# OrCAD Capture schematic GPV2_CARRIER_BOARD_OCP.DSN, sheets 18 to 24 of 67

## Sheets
18 023 PCIE SWITCH UART: size C
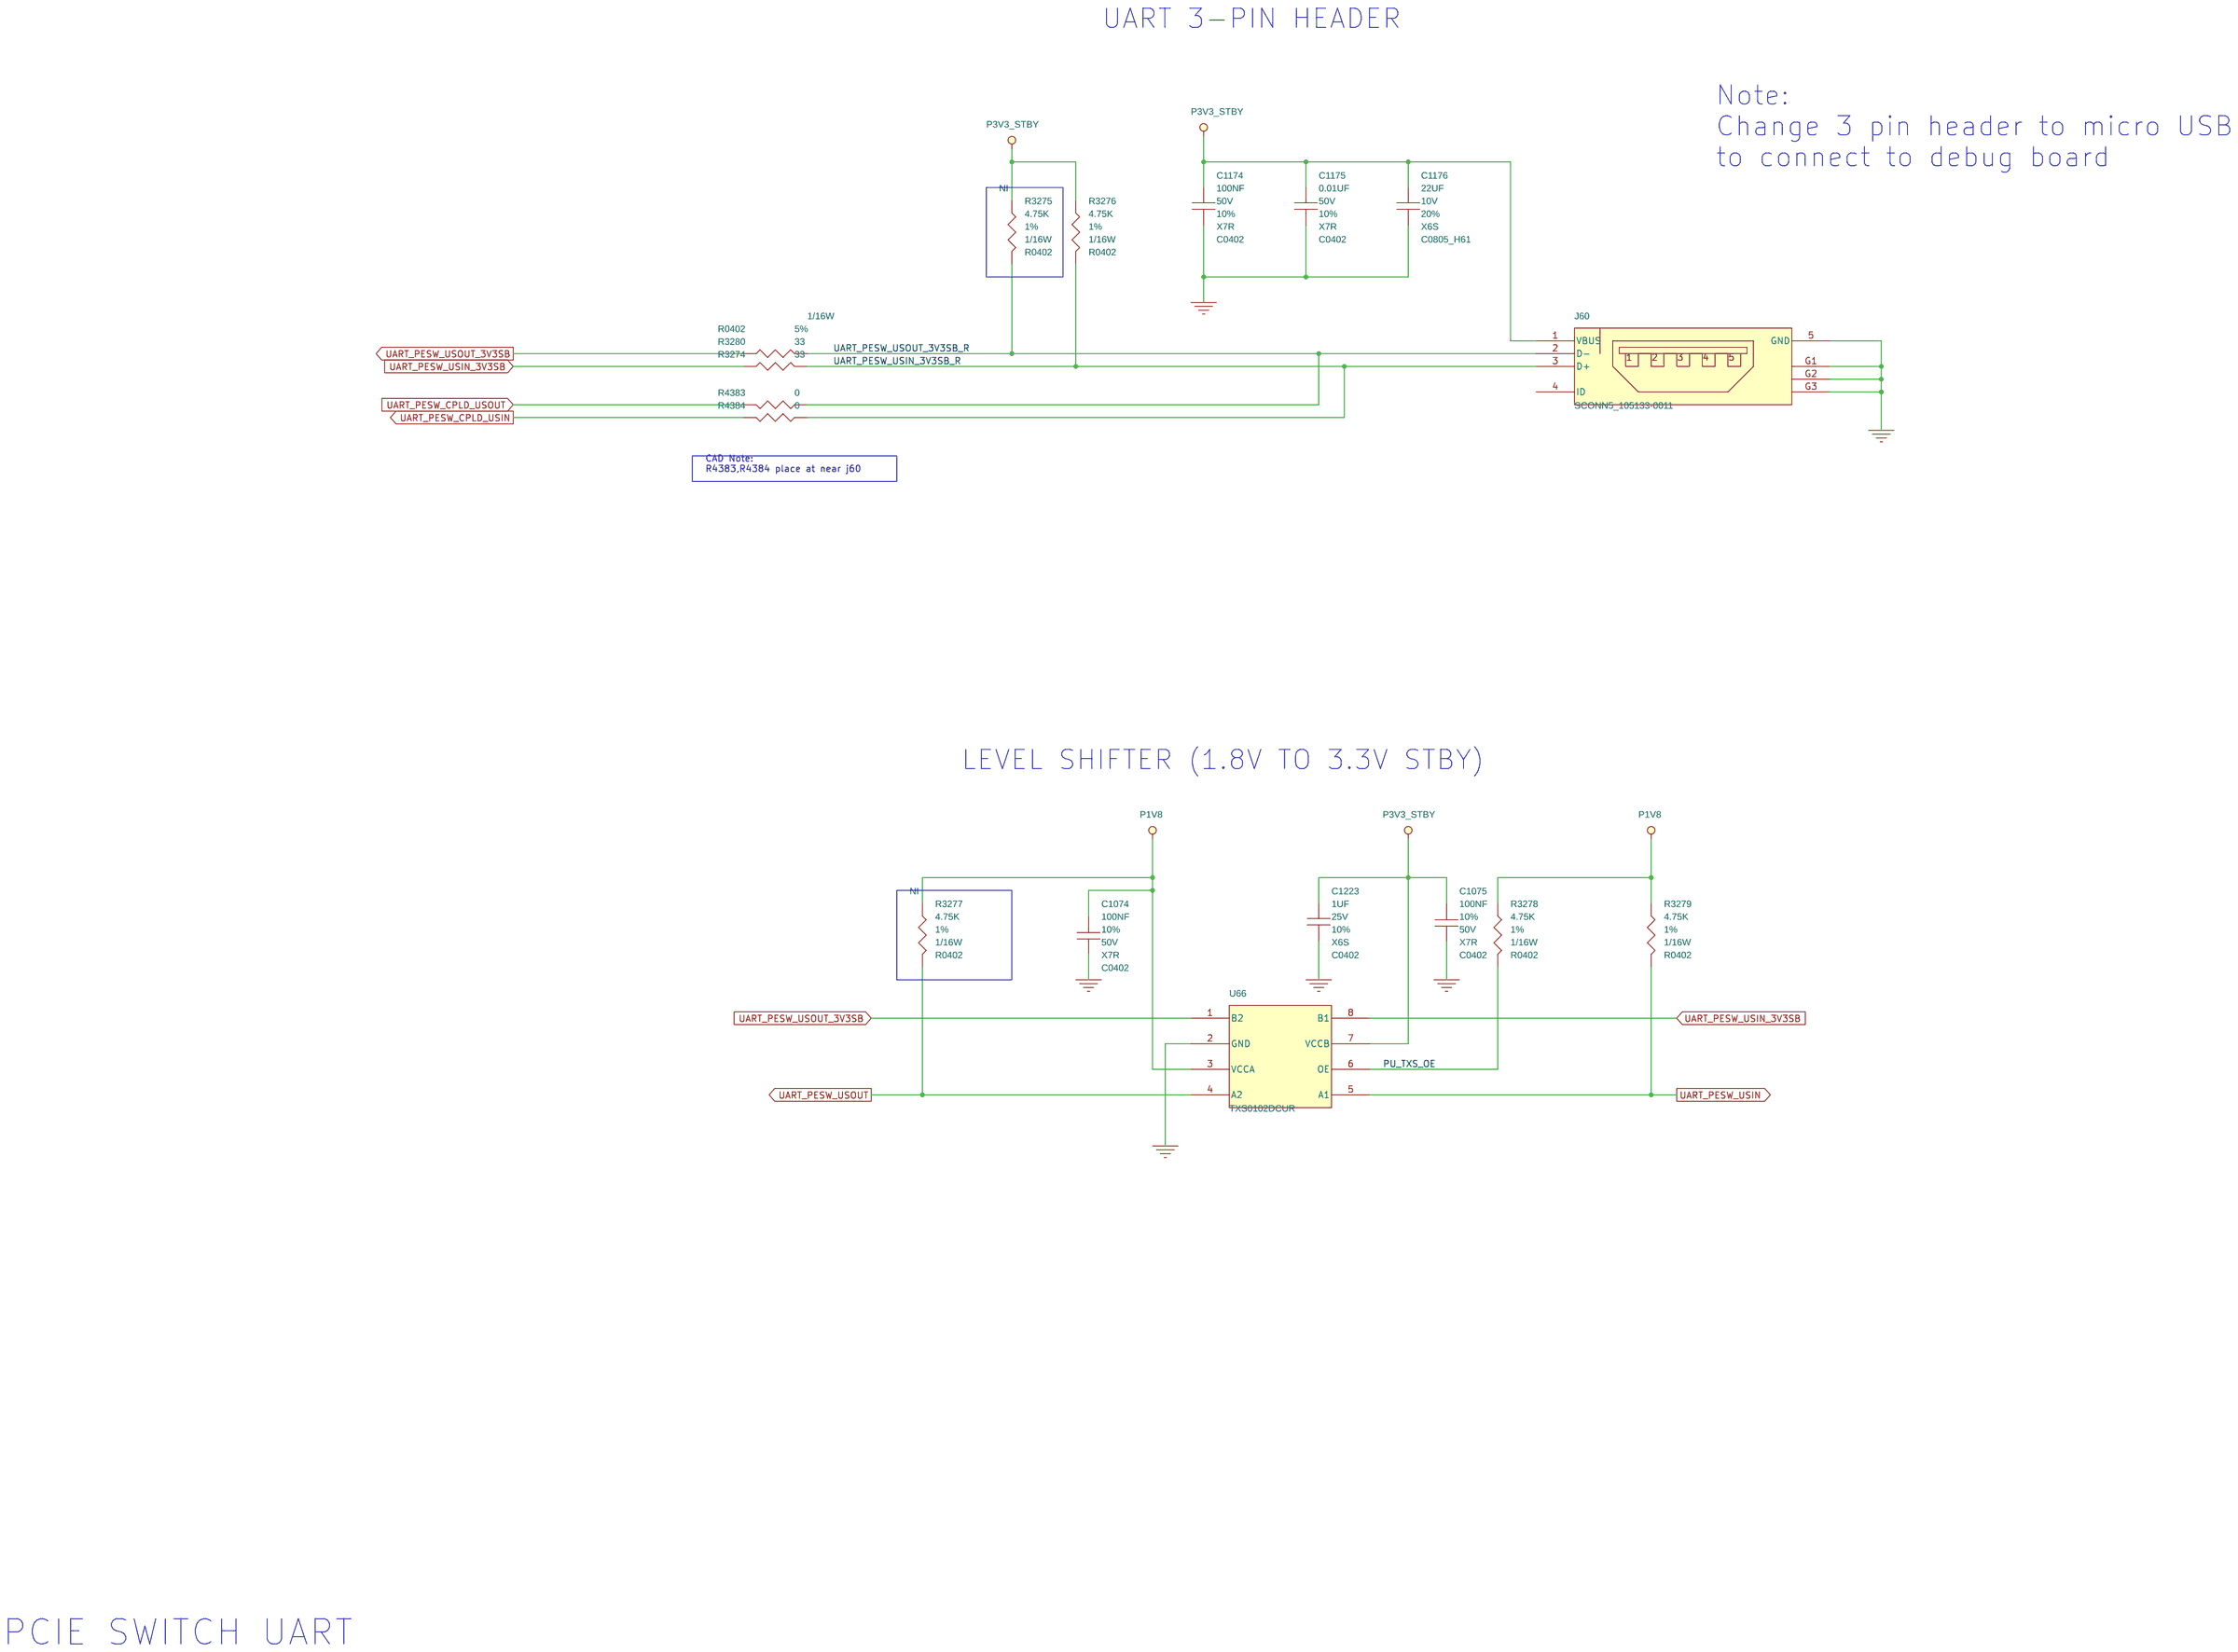
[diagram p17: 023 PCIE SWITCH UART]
19 024 100MHz CLOCK GEN: size C
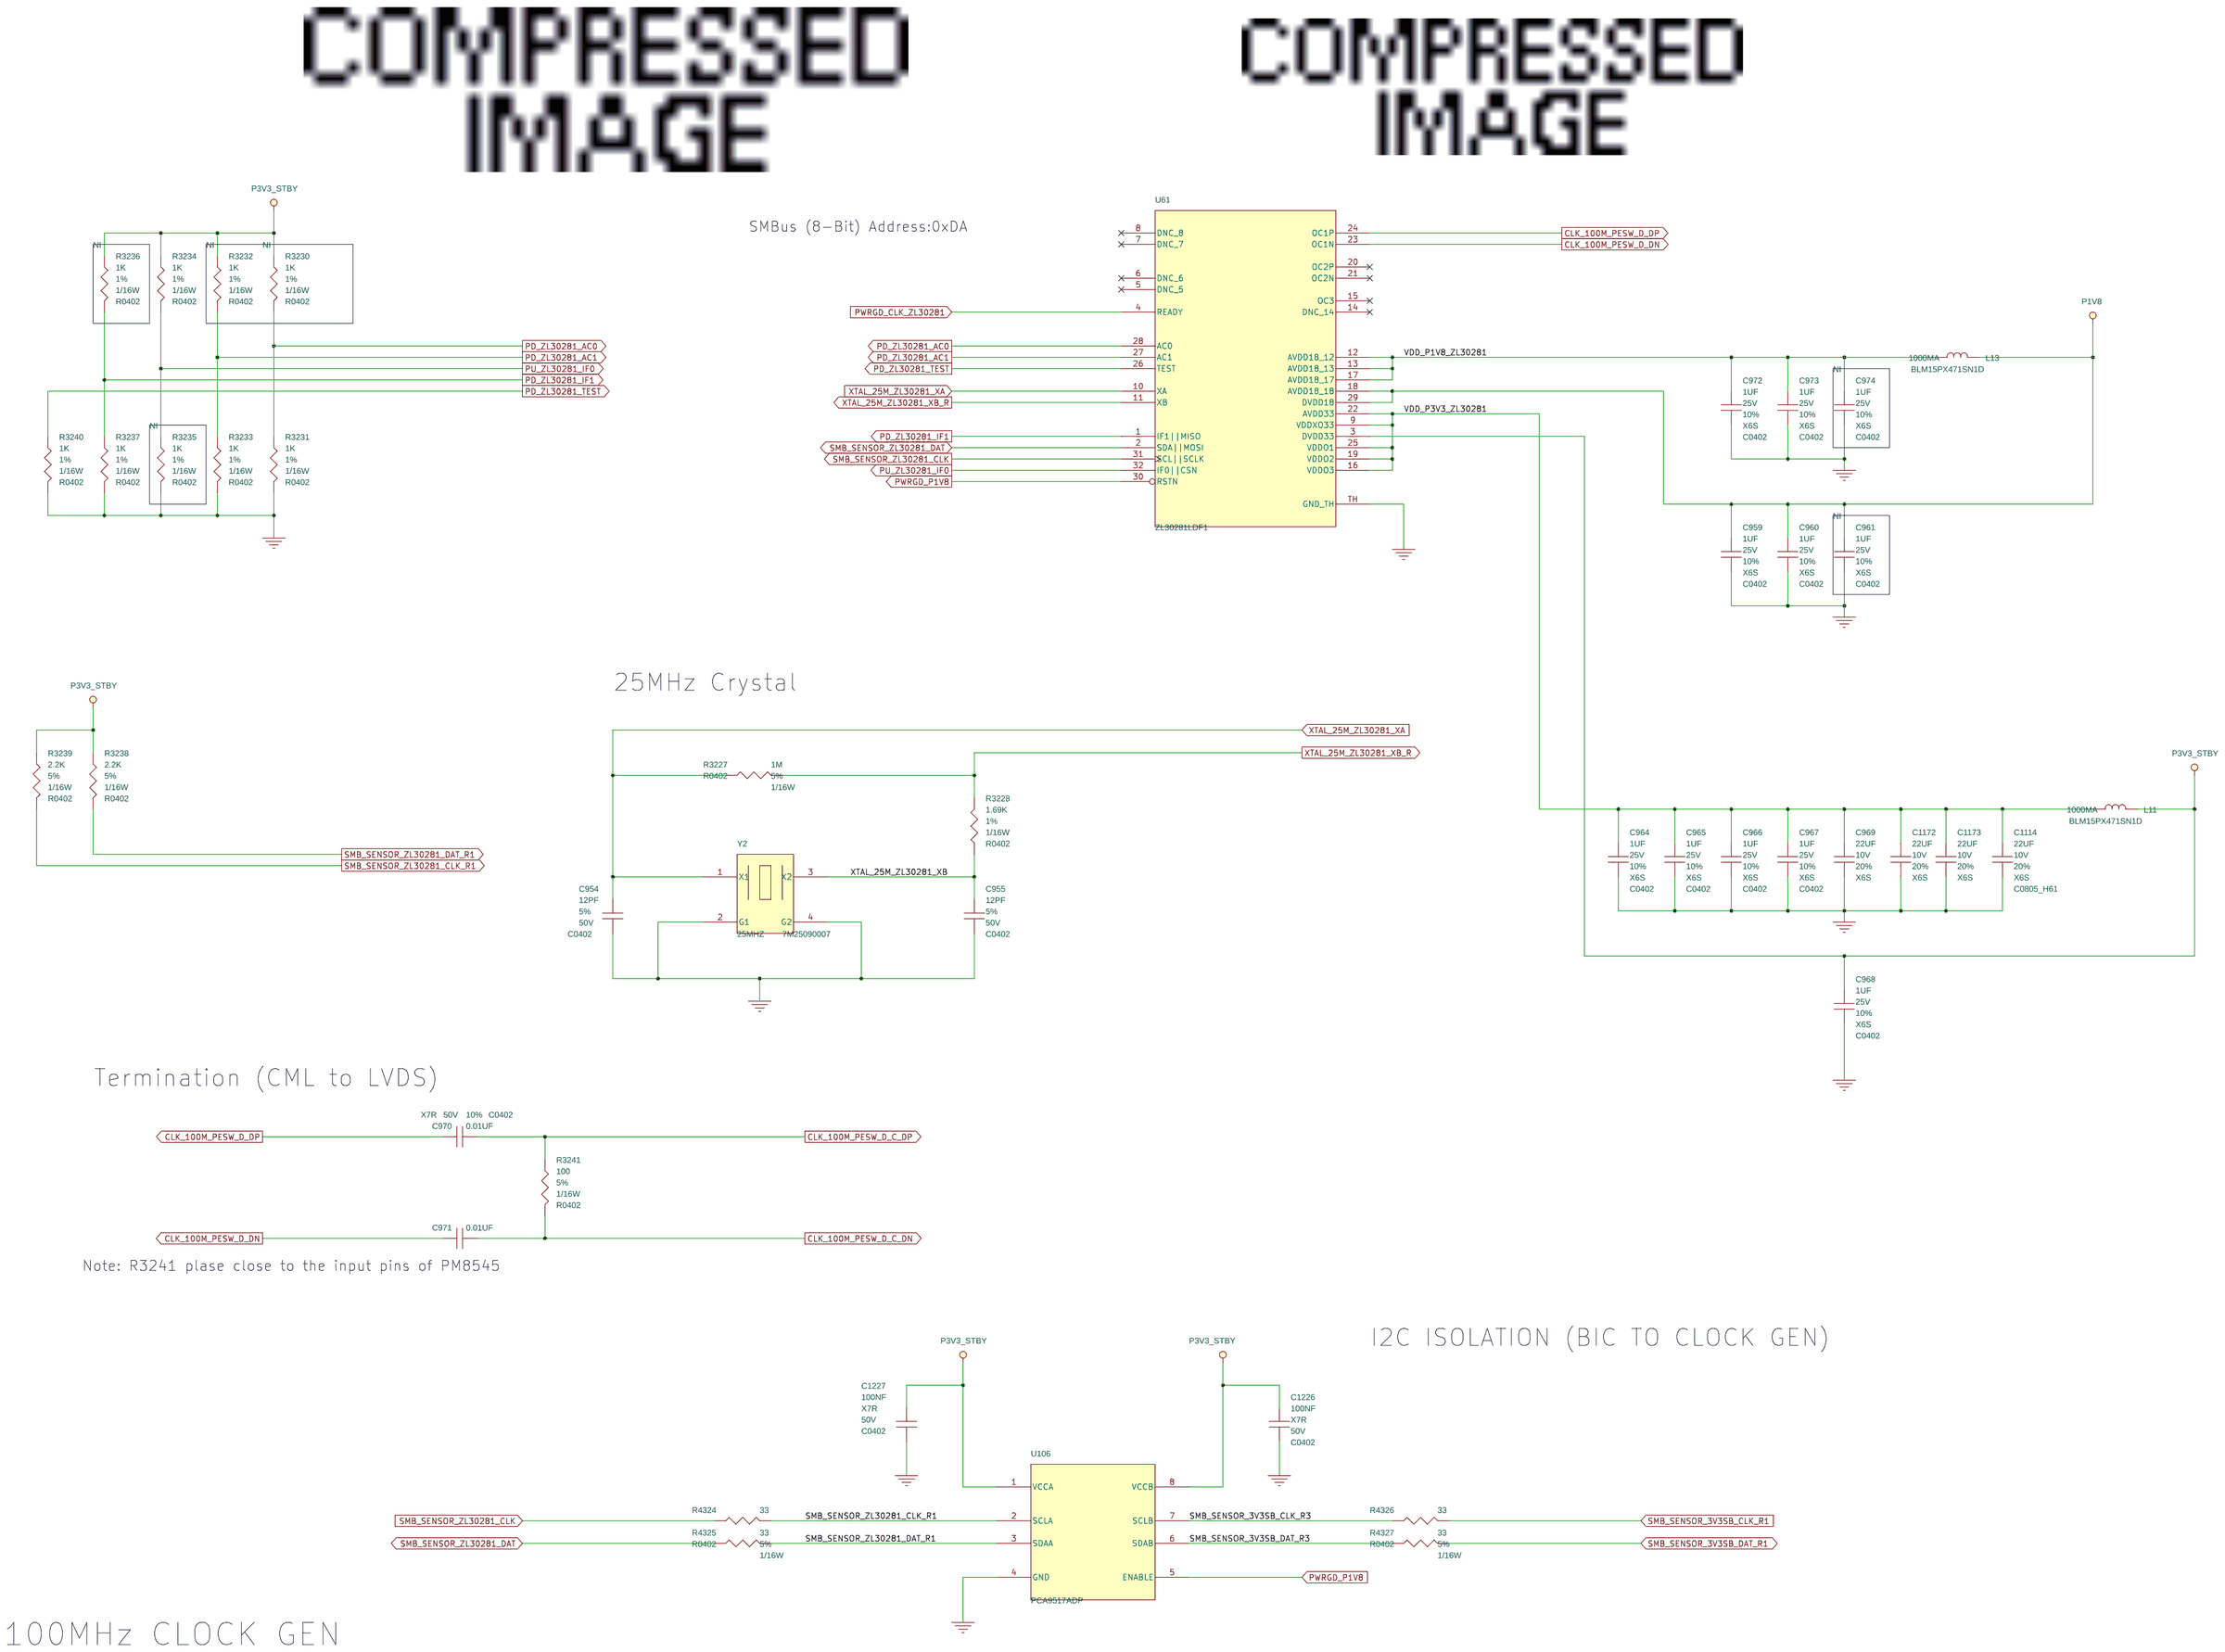
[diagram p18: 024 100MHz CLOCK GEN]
20 025 CLOCK BUFFER 1: size C
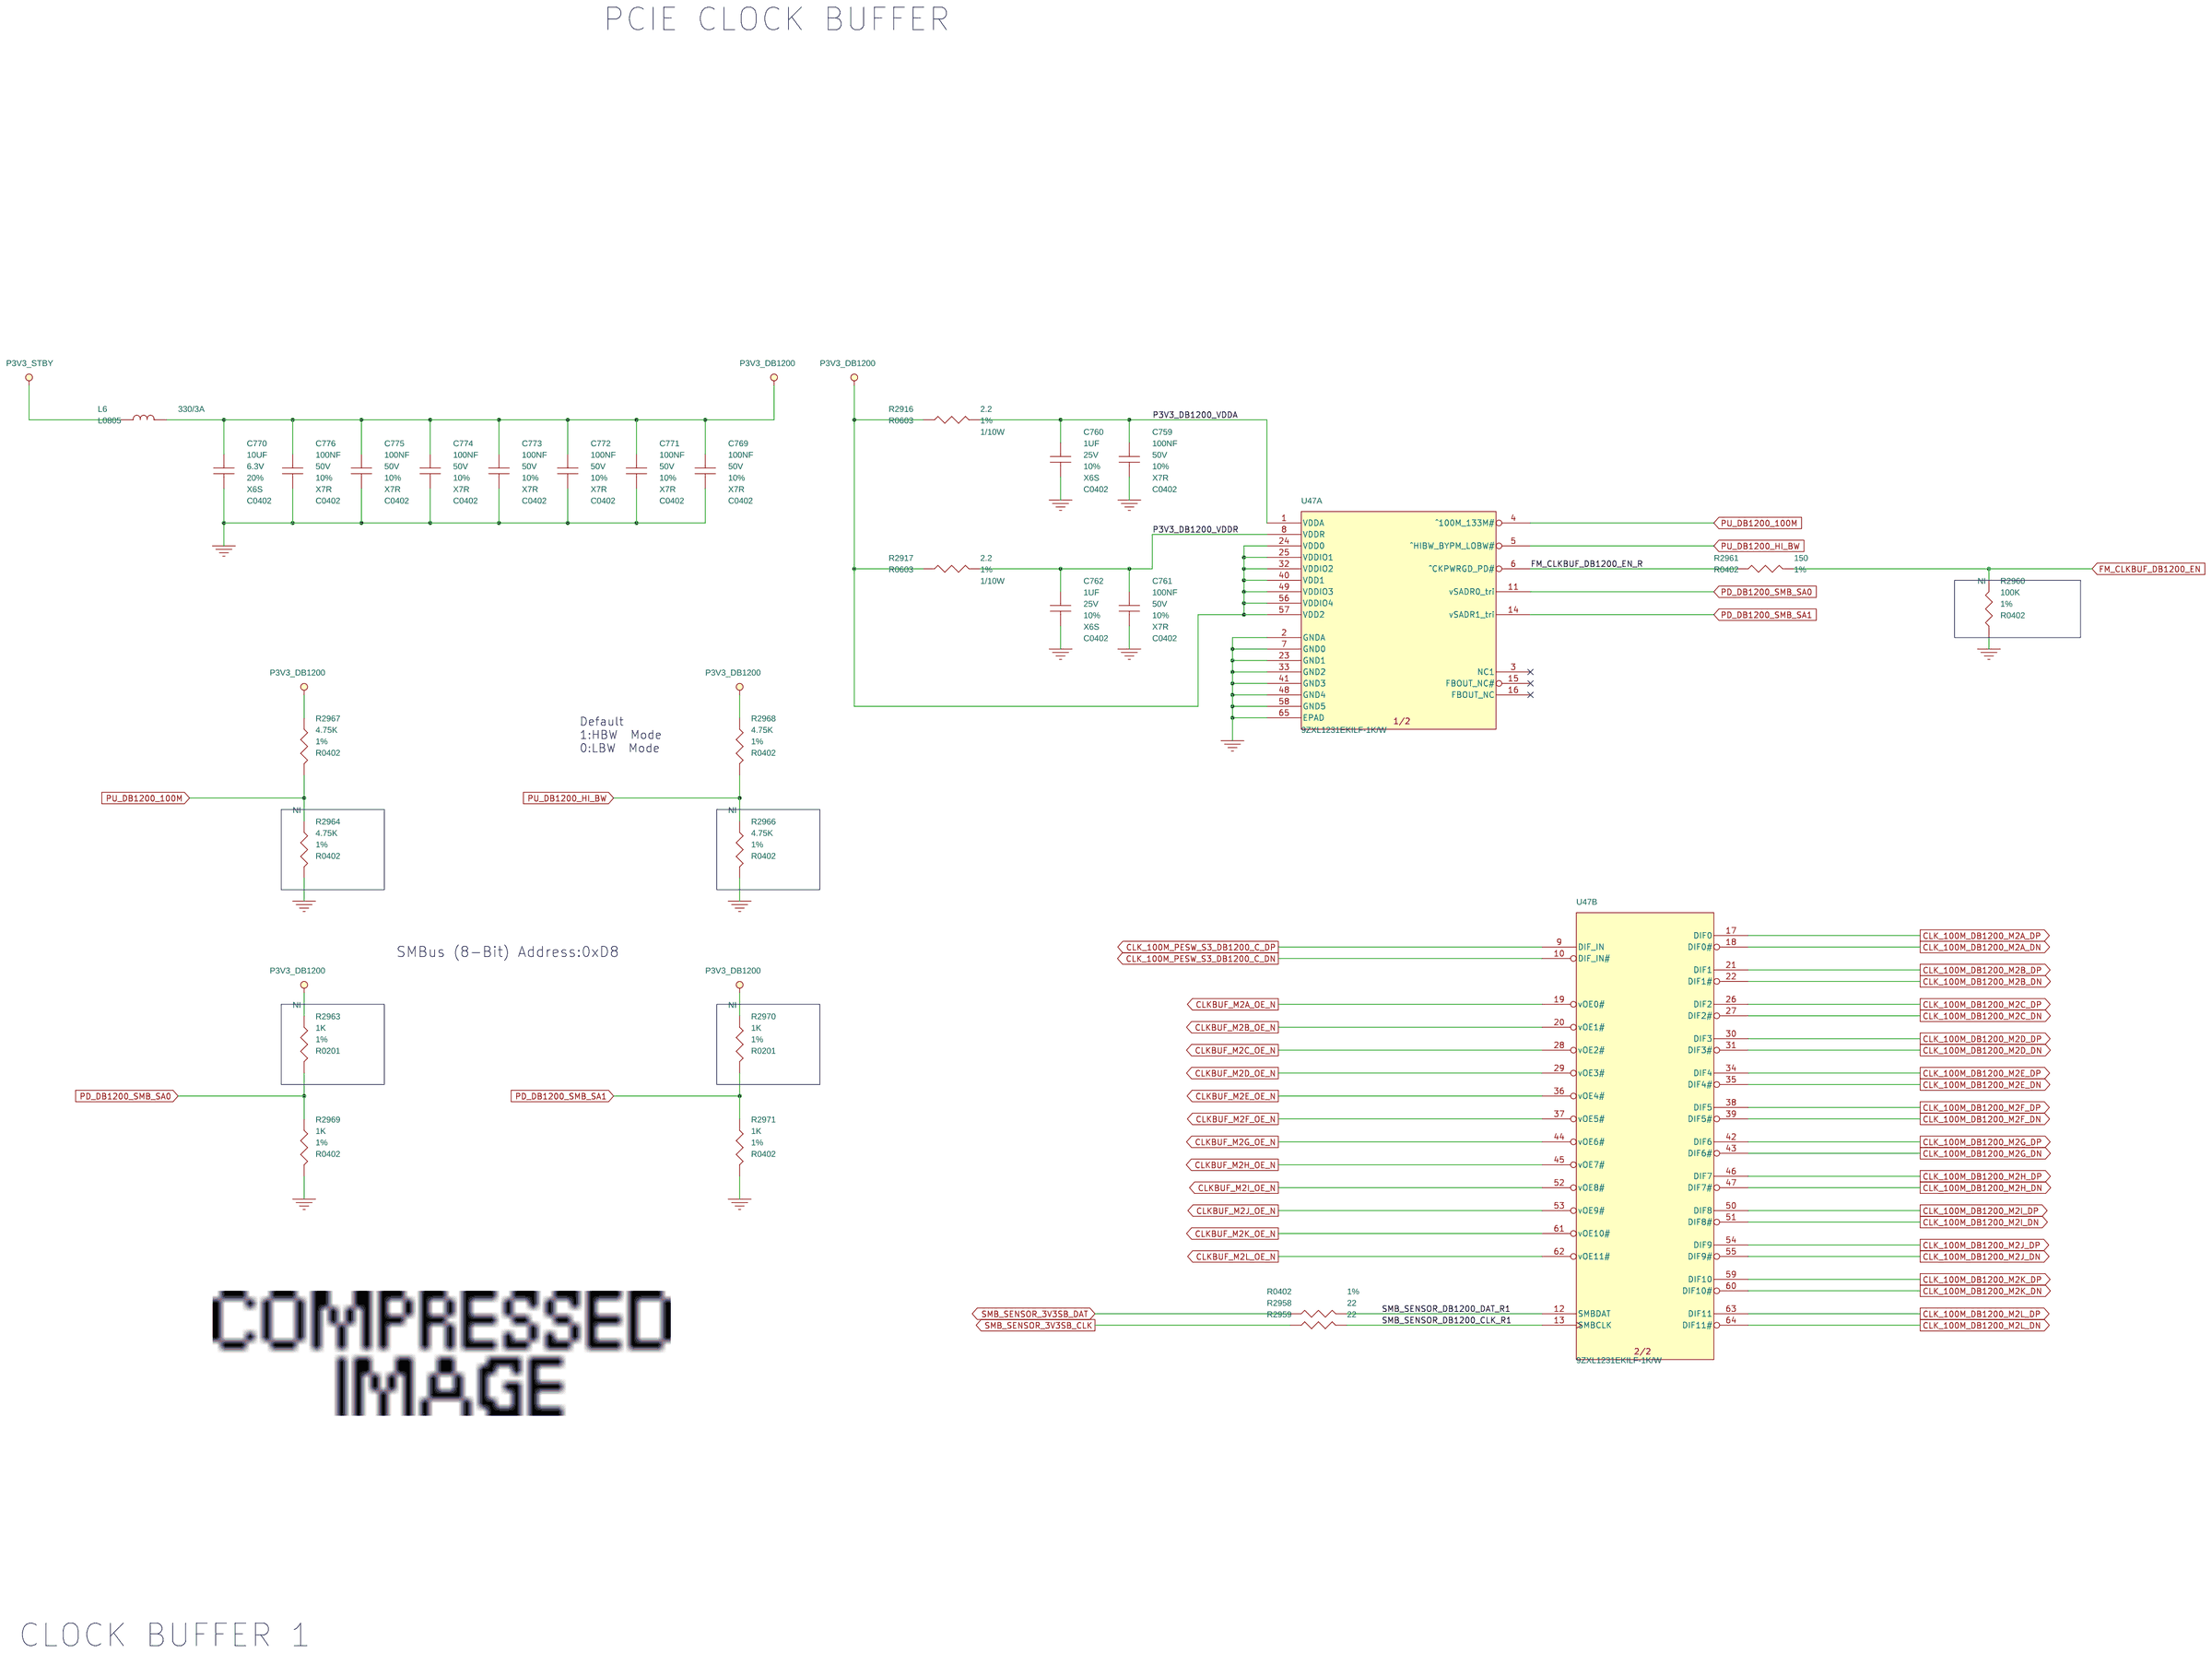
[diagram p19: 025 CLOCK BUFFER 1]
21 026 CLOCK BUFFER 2: size C
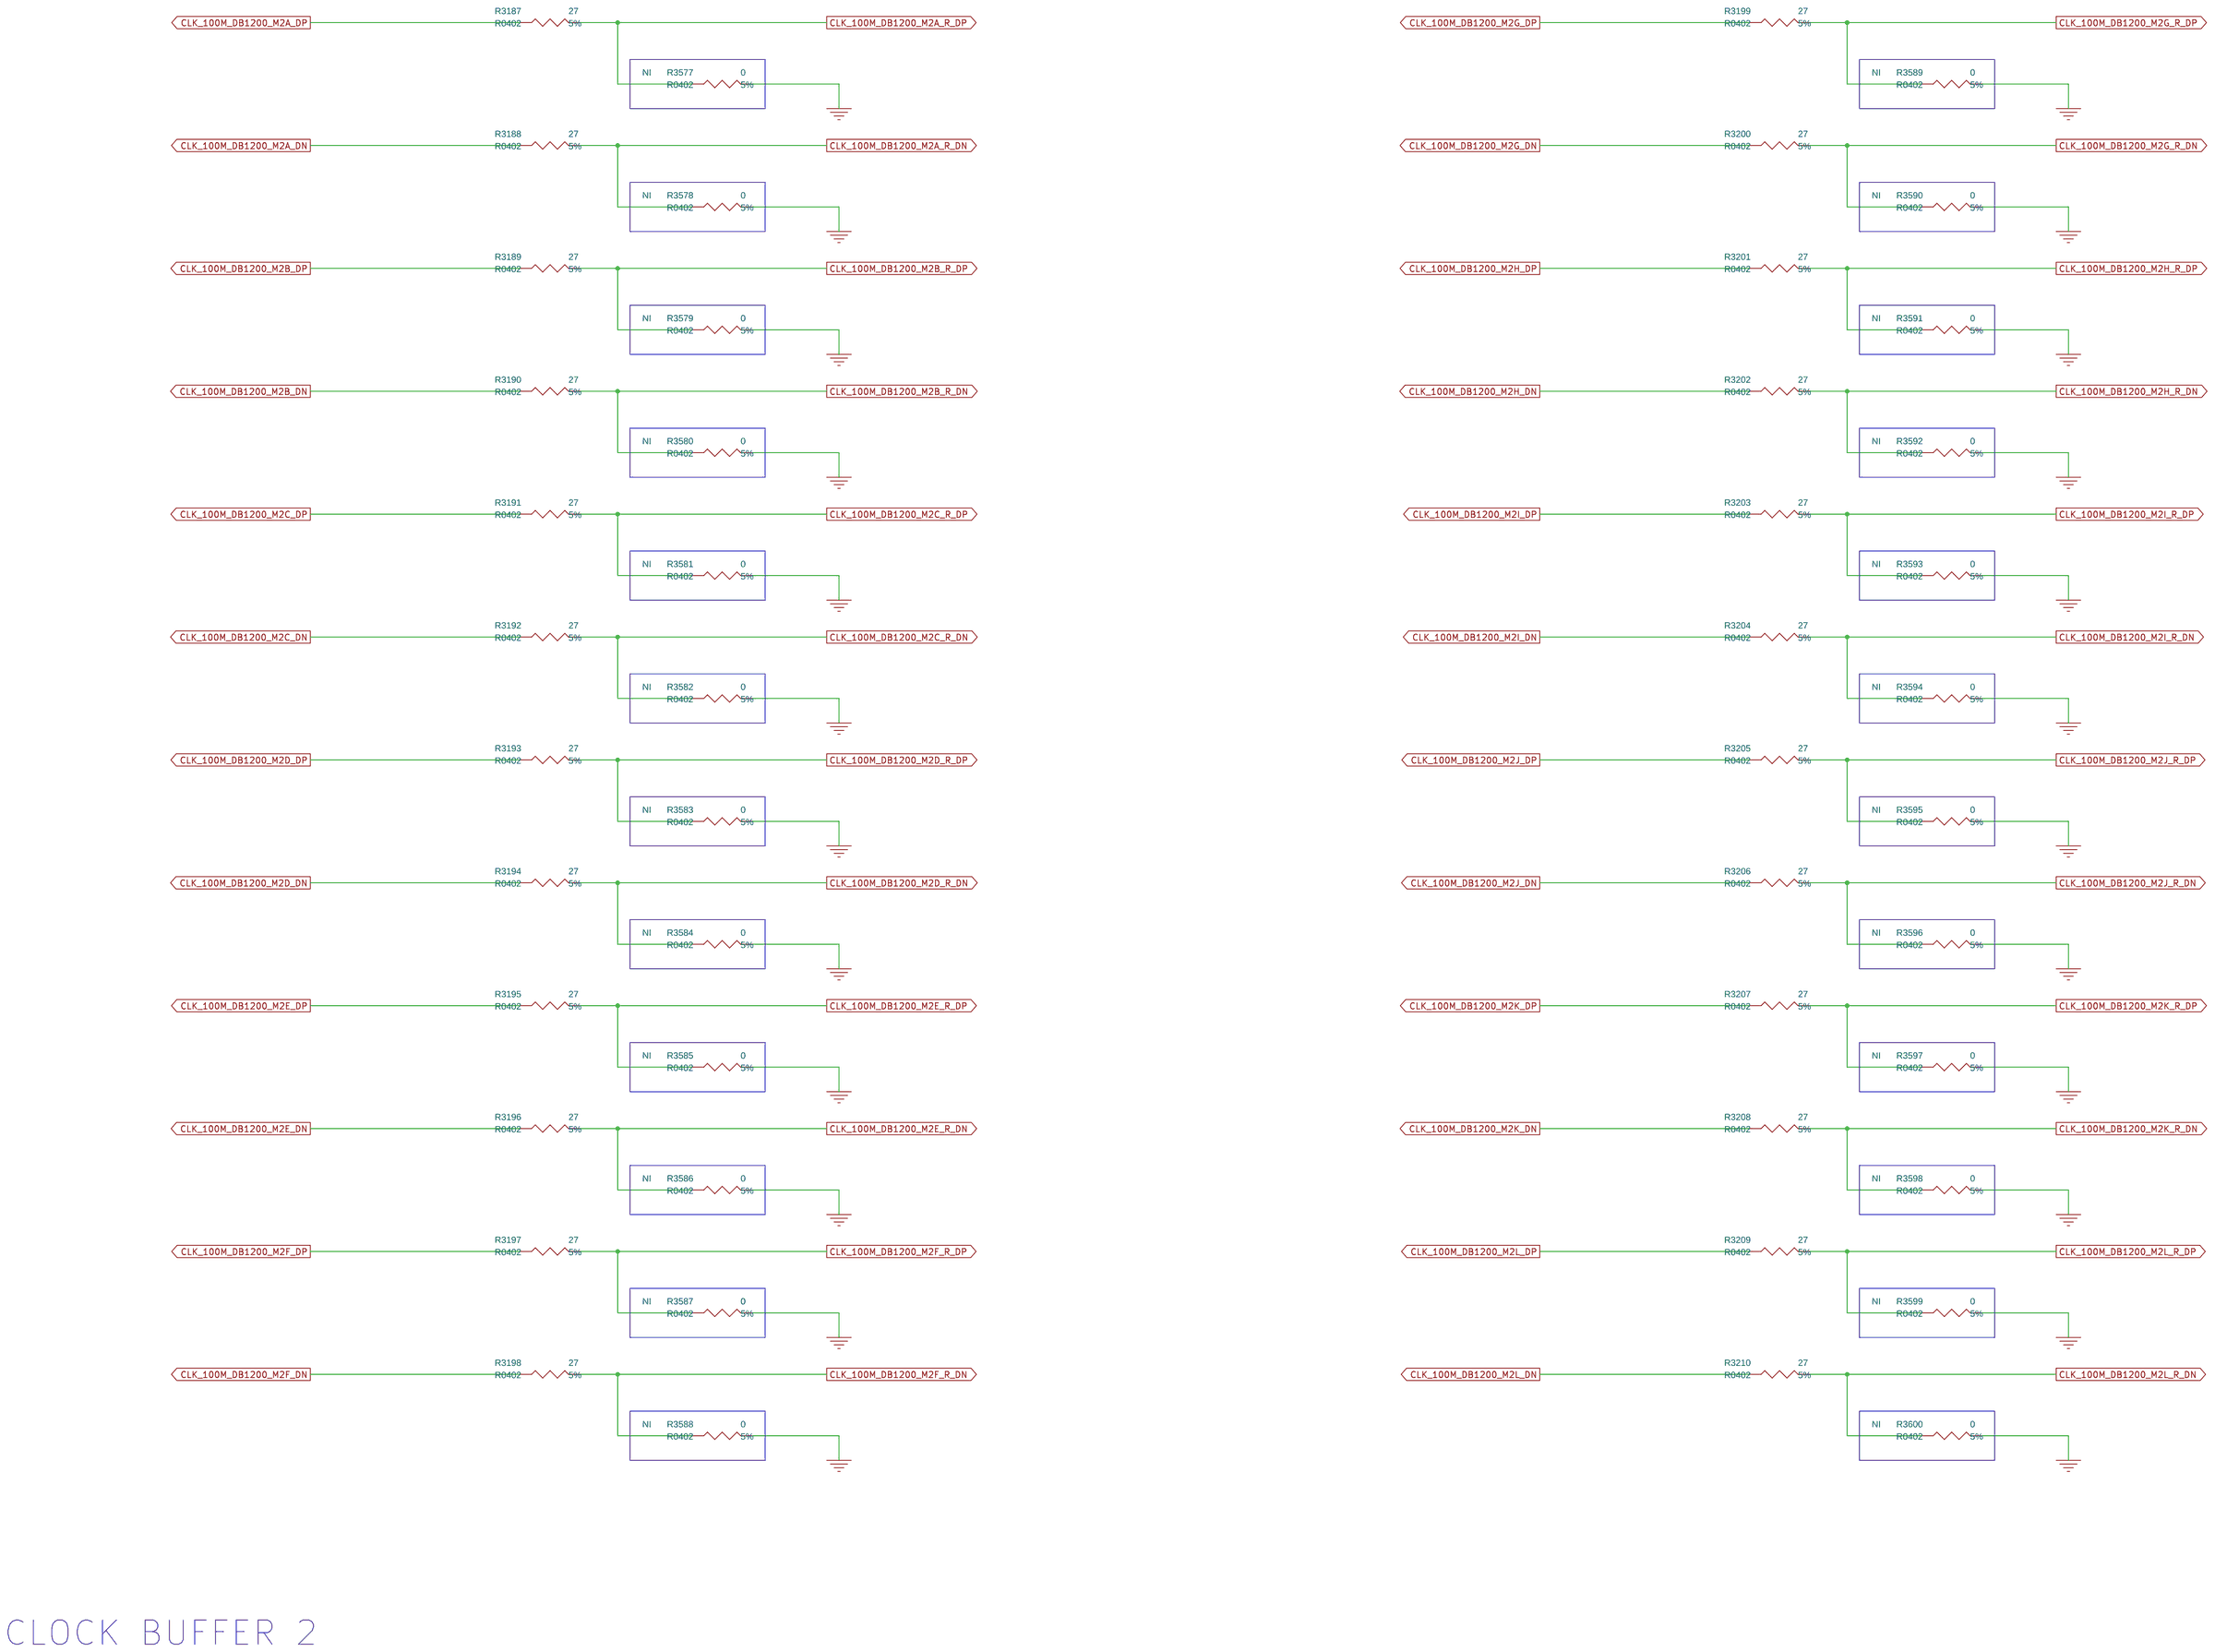
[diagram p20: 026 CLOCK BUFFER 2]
22 027 LEVEL SHIFTER 1: size C
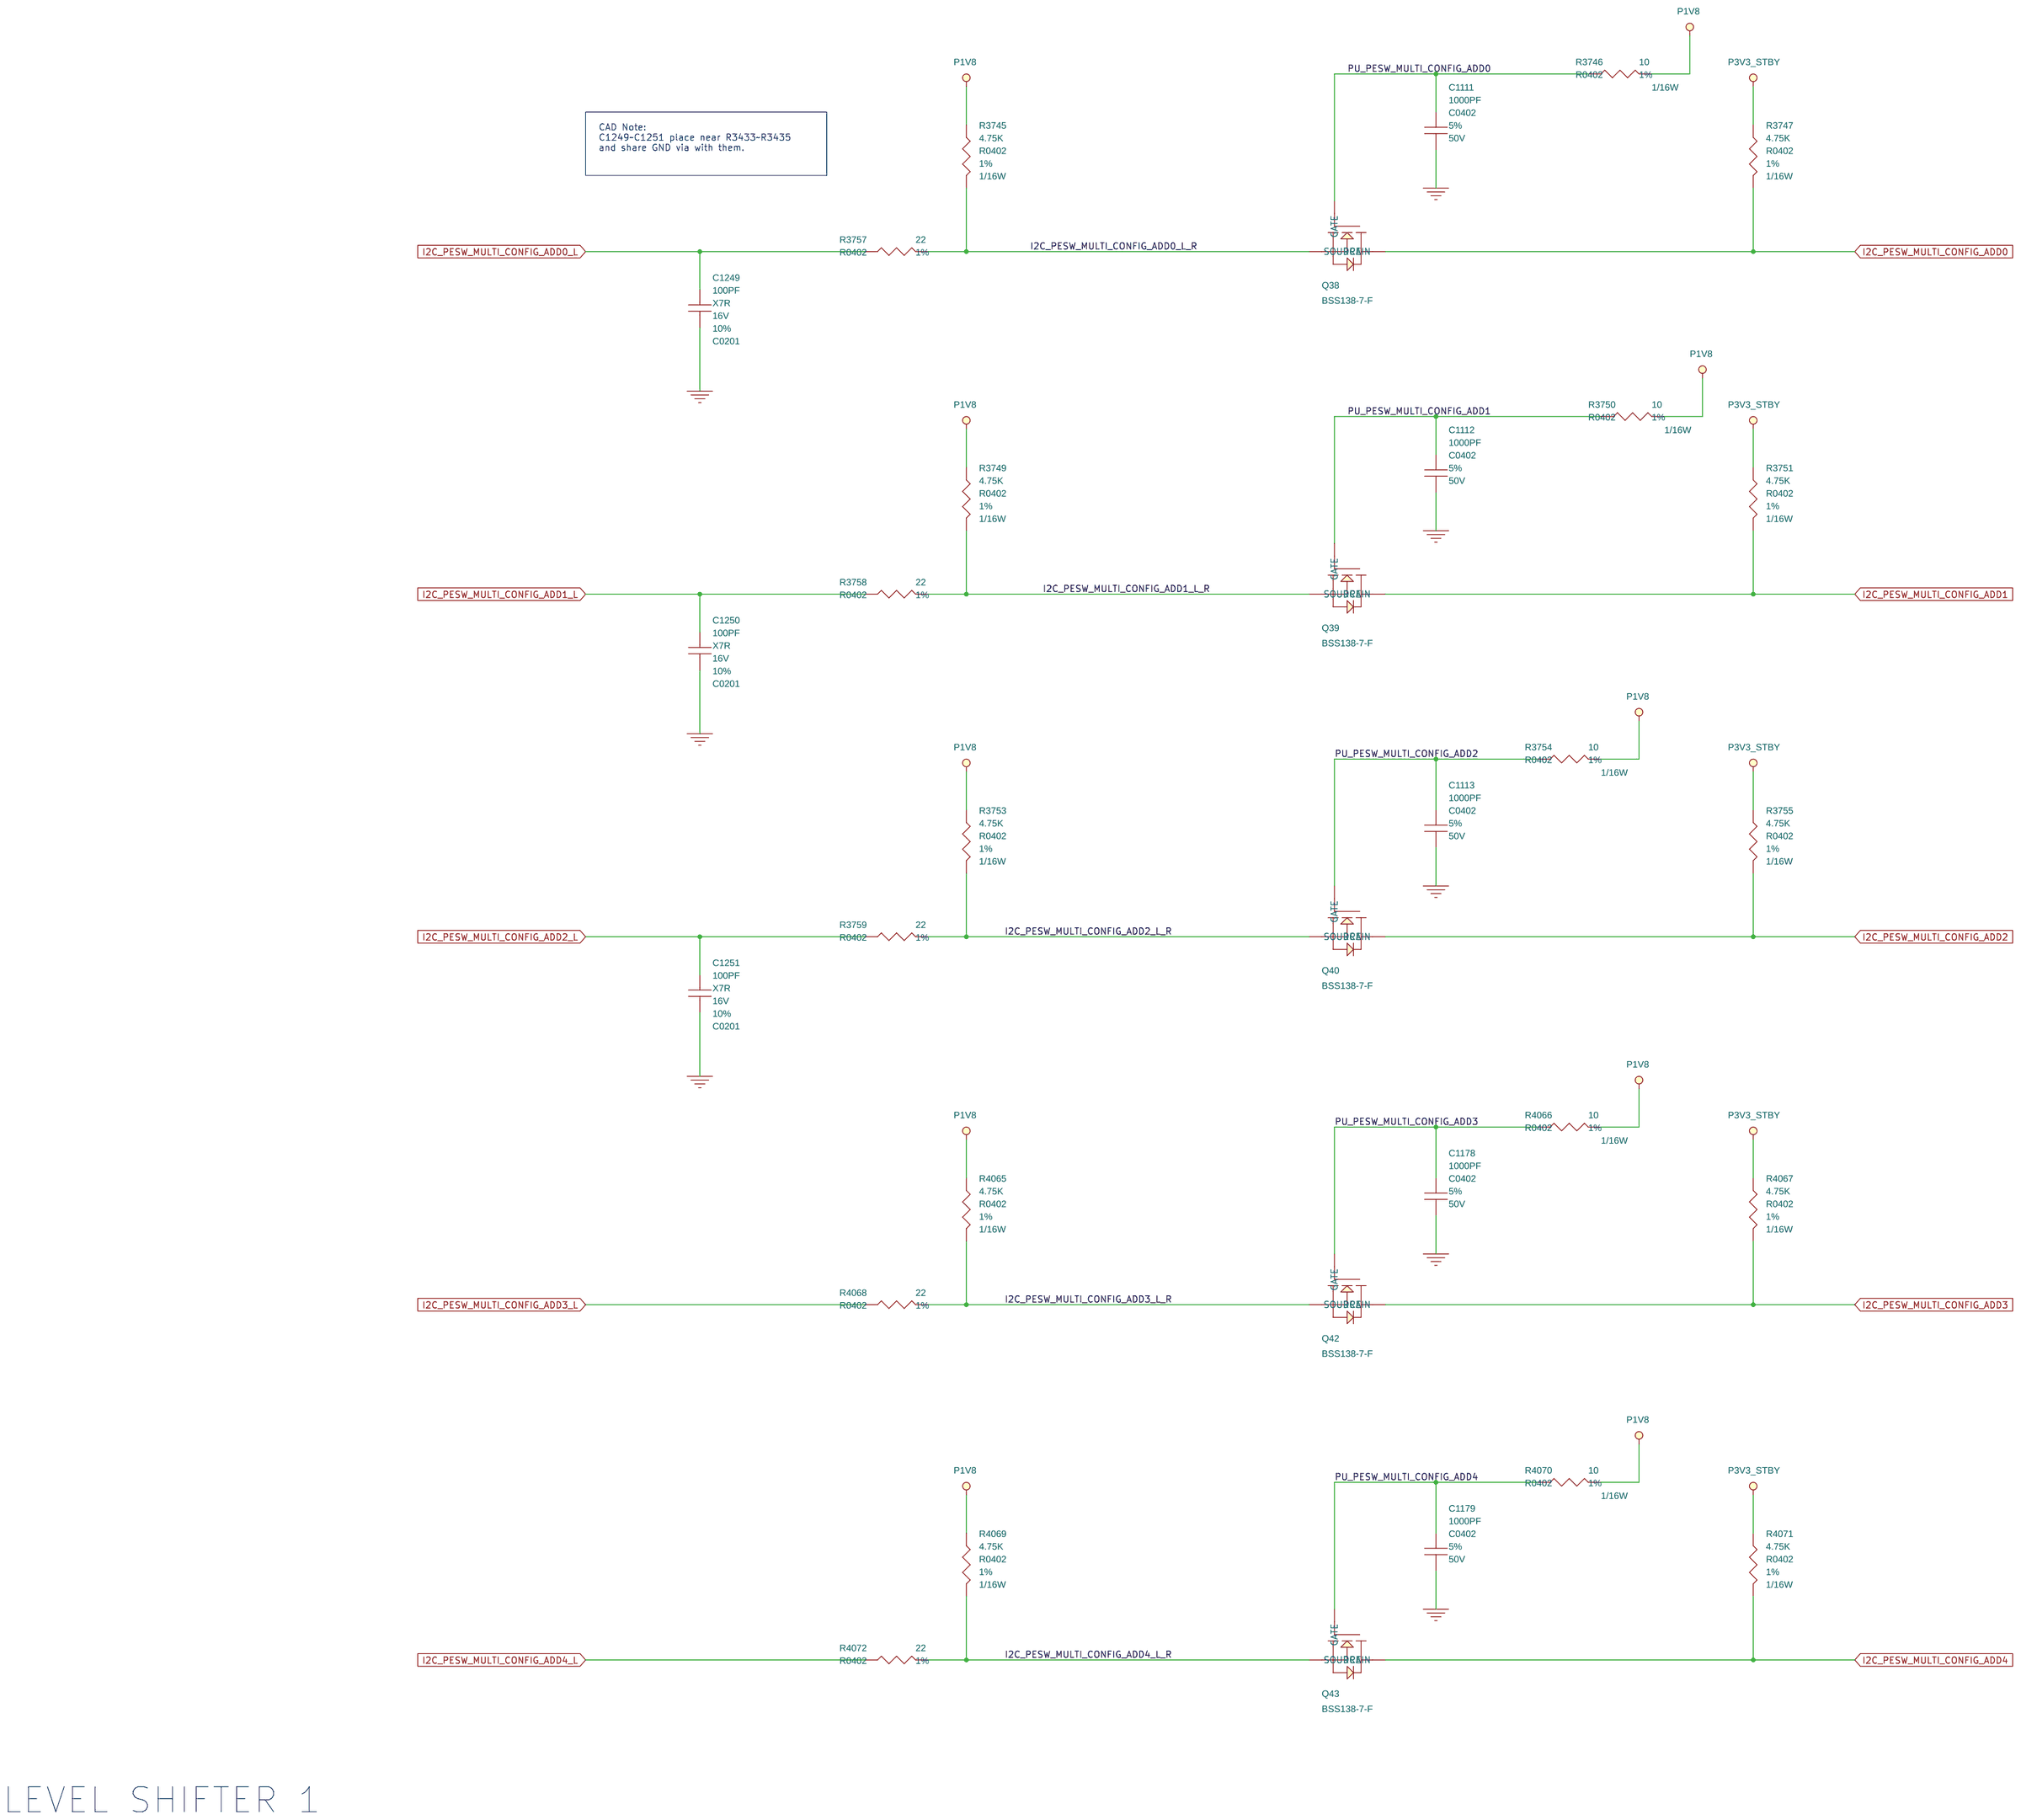
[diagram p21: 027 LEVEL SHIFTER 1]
23 028 LEVEL SHIFTER 2: size C
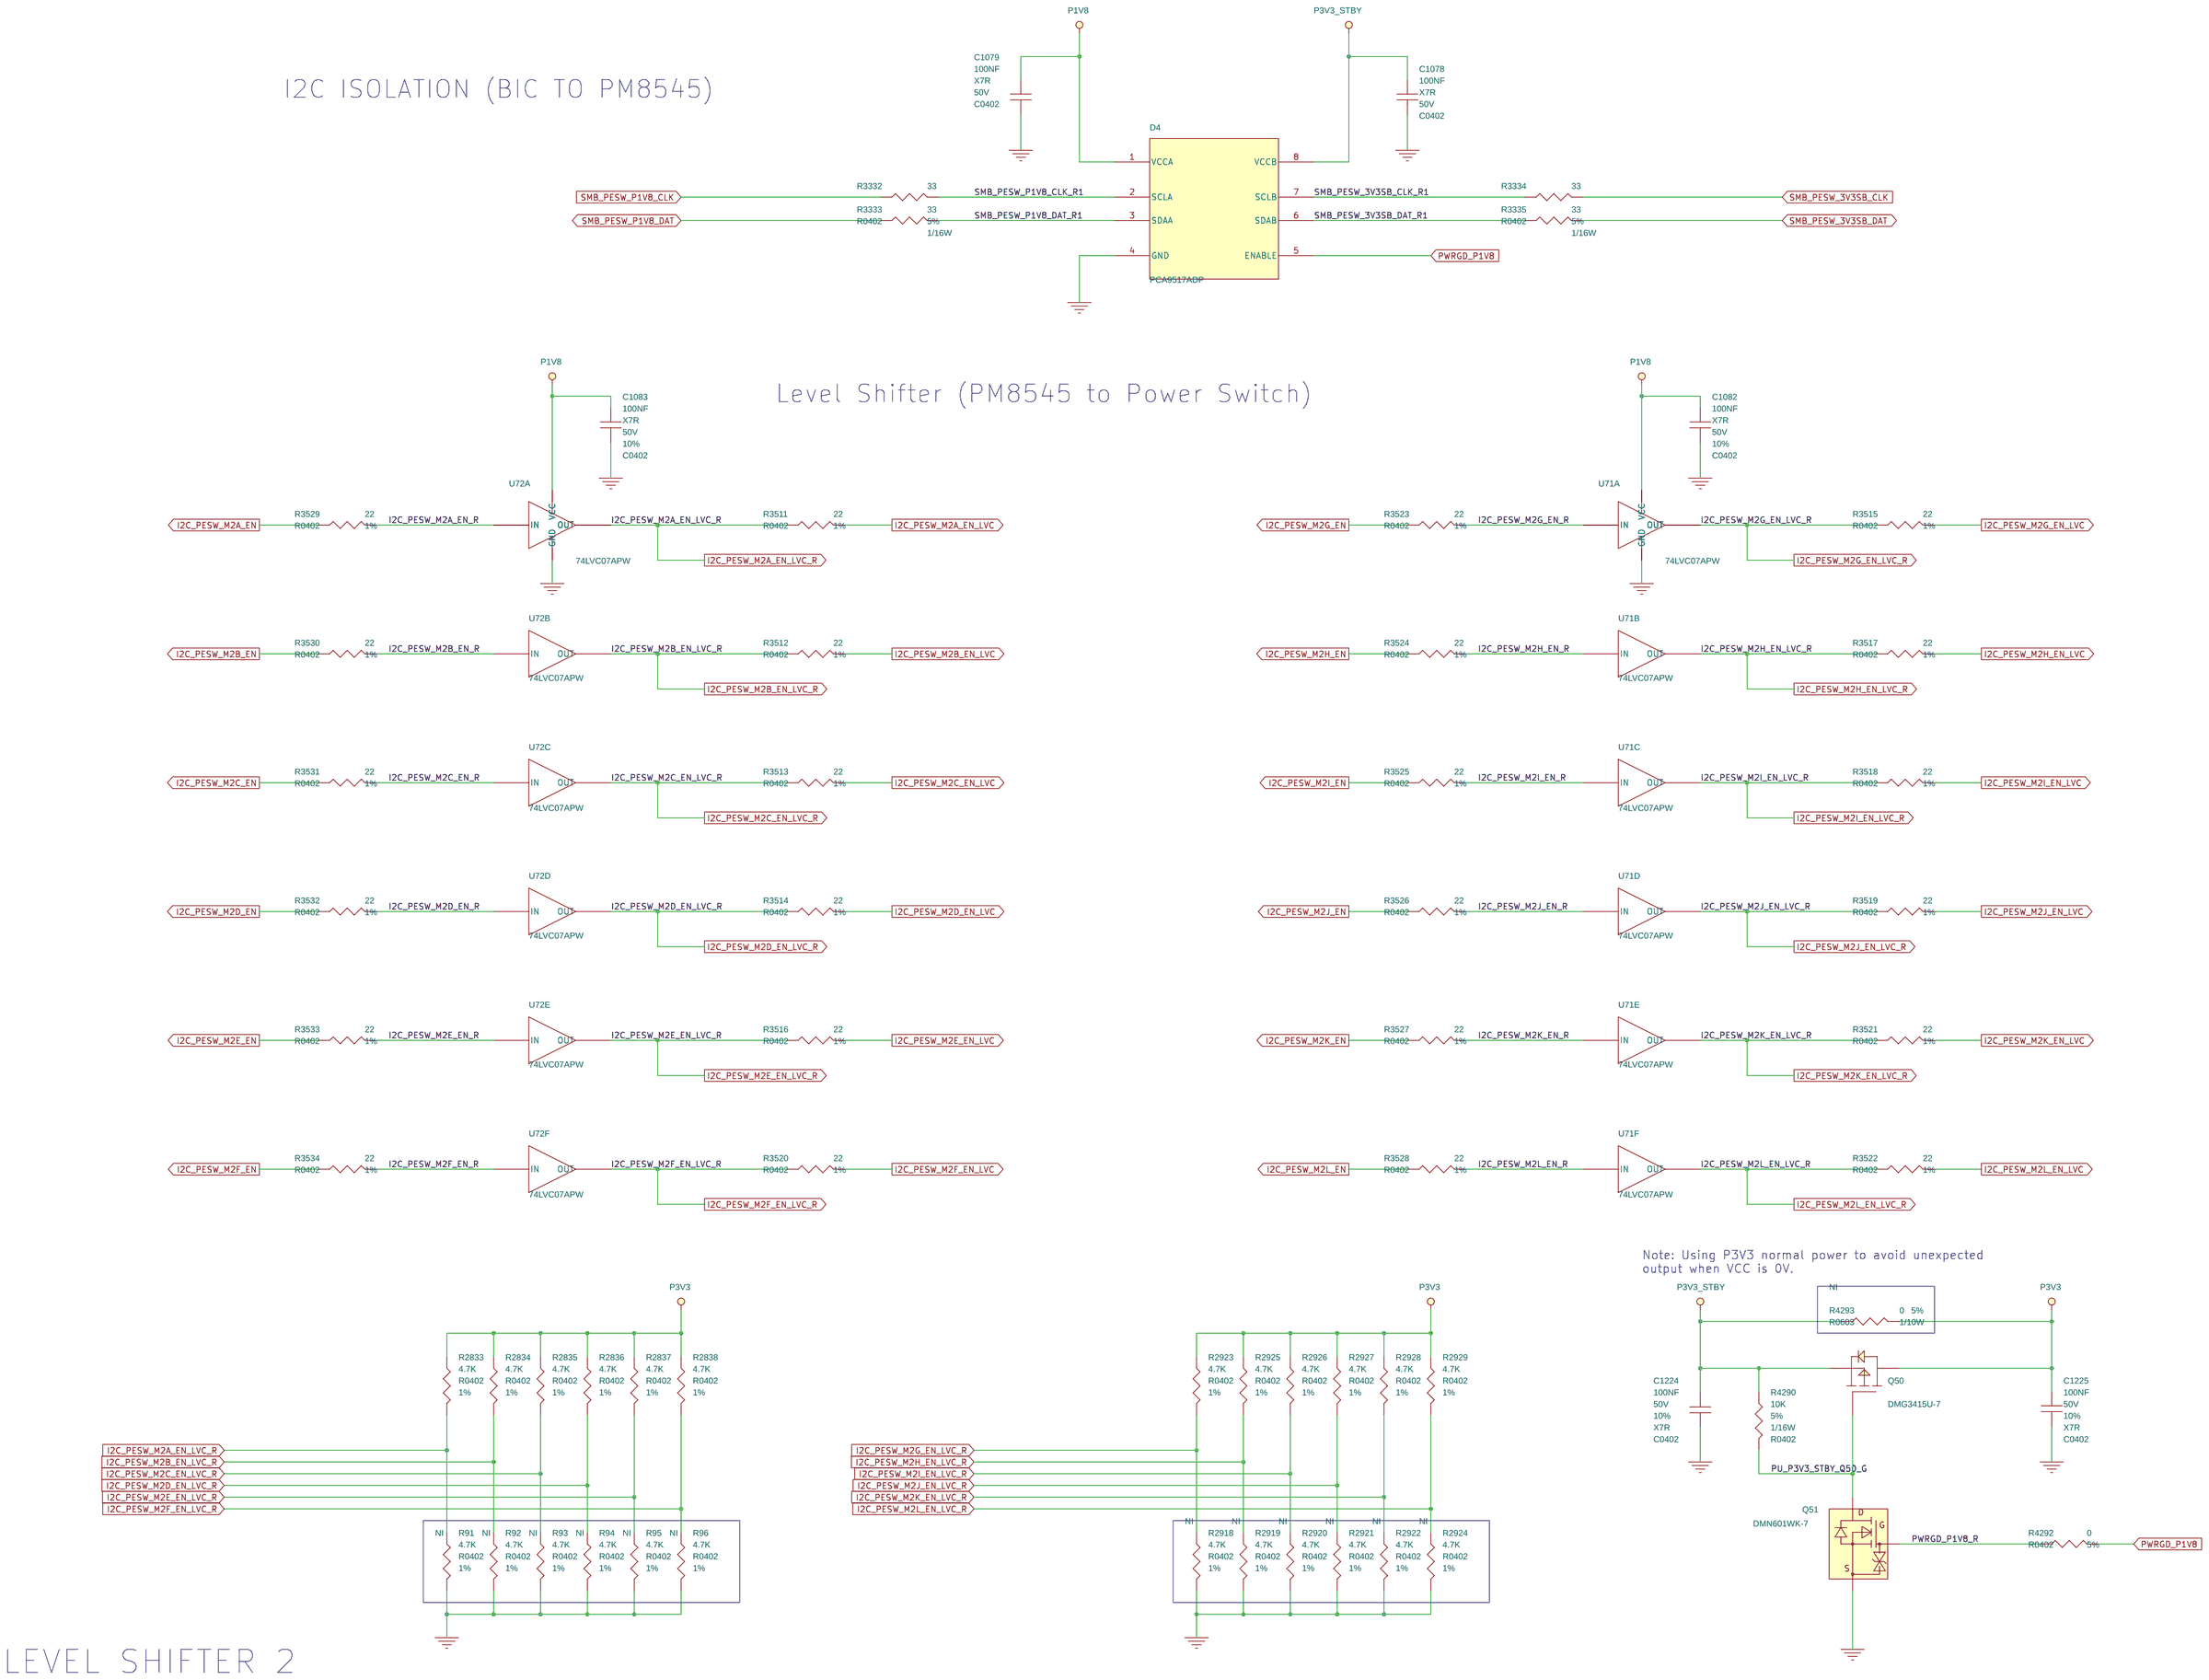
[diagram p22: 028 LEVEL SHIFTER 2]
24 029 M.2_A: size C
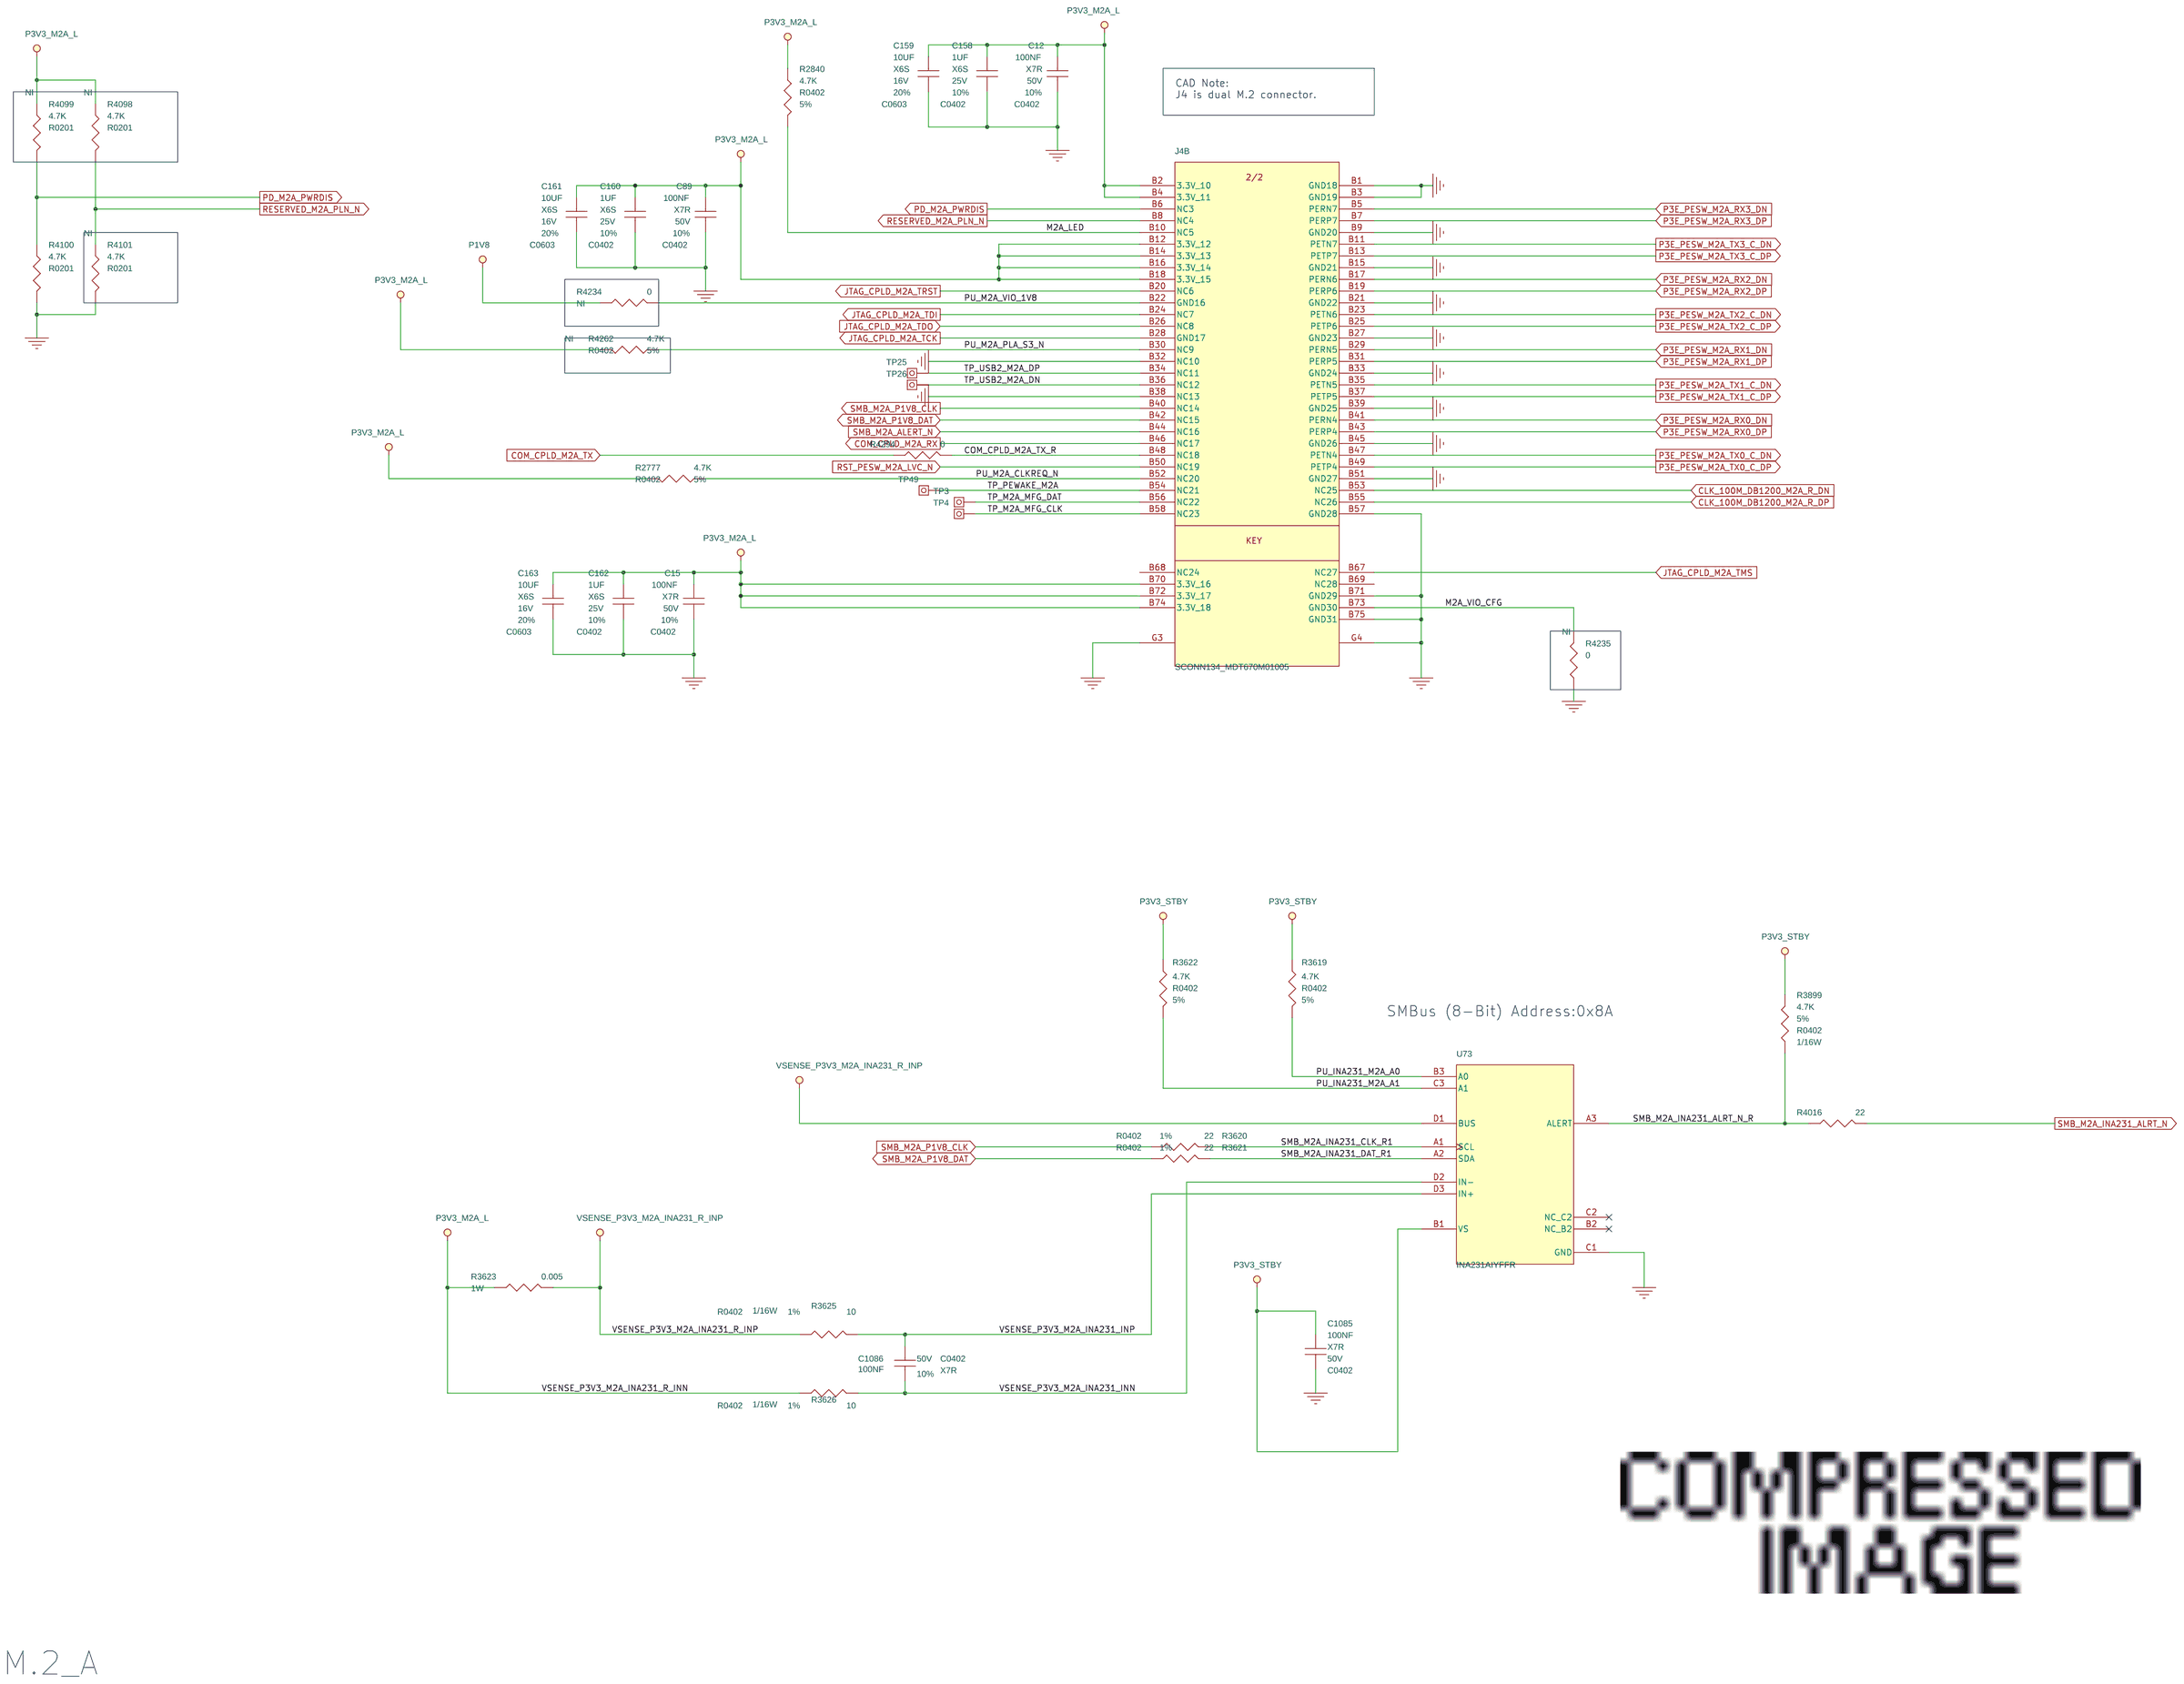
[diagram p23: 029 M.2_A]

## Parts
sheet 023 PCIE SWITCH UART
C1074  100NF  [C0402]
C1075  100NF  [C0402]
C1174  100NF  [C0402]
C1175  0.01UF  [C0402]
C1176  22UF  [C0805_H61]
C1223  1UF  [C0402]
J60  SCONN5_105133-0011  [USB1XAY]
R3274  33  [R0402]
R3275  4.75K  [R0402]
R3276  4.75K  [R0402]
R3277  4.75K  [R0402]
R3278  4.75K  [R0402]
R3279  4.75K  [R0402]
R3280  33  [R0402]
R4383  0  [R0402]
R4384  0  [R0402]
U66  TXS0102DCUR  [VSSOP8XB]
sheet 024 100MHz CLOCK GEN
C954  12PF  [C0402]
C955  12PF  [C0402]
C959  1UF  [C0402]
C960  1UF  [C0402]
C961  1UF  [C0402]
C964  1UF  [C0402]
C965  1UF  [C0402]
C966  1UF  [C0402]
C967  1UF  [C0402]
C968  1UF  [C0402]
C969  22UF  [C0805_H61]
C970  0.01UF  [C0402]
C971  0.01UF  [C0402]
C972  1UF  [C0402]
C973  1UF  [C0402]
C974  1UF  [C0402]
C1114  22UF  [C0805_H61]
C1172  22UF  [C0805_H61]
C1173  22UF  [C0805_H61]
C1226  100NF  [C0402]
C1227  100NF  [C0402]
L11  BLM15PX471SN1D  [L0402]
L13  BLM15PX471SN1D  [L0402]
R3227  1M  [R0402]
R3228  1.69K  [R0402]
R3230  1K  [R0402]
R3231  1K  [R0402]
R3232  1K  [R0402]
R3233  1K  [R0402]
R3234  1K  [R0402]
R3235  1K  [R0402]
R3236  1K  [R0402]
R3237  1K  [R0402]
R3238  2.2K  [R0402]
R3239  2.2K  [R0402]
R3240  1K  [R0402]
R3241  100  [R0402]
R4324  33  [R0402]
R4325  33  [R0402]
R4326  33  [R0402]
R4327  33  [R0402]
U61  ZL30281LDF1  [QFN32_TH_0-5_5X5XL]
U106  PCA9517ADP  [TSSOP8_3]
Y2  25MHZ  [X_4S_7M25000083_3-2X2-5]
sheet 025 CLOCK BUFFER 1
C759  100NF  [C0402]
C760  1UF  [C0402]
C761  100NF  [C0402]
C762  1UF  [C0402]
C769  100NF  [C0402]
C770  10UF  [C0402]
C771  100NF  [C0402]
C772  100NF  [C0402]
C773  100NF  [C0402]
C774  100NF  [C0402]
C775  100NF  [C0402]
C776  100NF  [C0402]
L6  330/3A  [L0805]
R2916  2.2  [R0603]
R2917  2.2  [R0603]
R2958  22  [R0402]
R2959  22  [R0402]
R2960  100K  [R0402]
R2961  150  [R0402]
R2963  1K  [R0201]
R2964  4.75K  [R0402]
R2966  4.75K  [R0402]
R2967  4.75K  [R0402]
R2968  4.75K  [R0402]
R2969  1K  [R0402]
R2970  1K  [R0201]
R2971  1K  [R0402]
U47  9ZXL1231EKILF-1K/W  [VFQFPN64_TH_0-5_9X9XA]  (sections A,B)
sheet 026 CLOCK BUFFER 2
R3187  27  [R0402]
R3188  27  [R0402]
R3189  27  [R0402]
R3190  27  [R0402]
R3191  27  [R0402]
R3192  27  [R0402]
R3193  27  [R0402]
R3194  27  [R0402]
R3195  27  [R0402]
R3196  27  [R0402]
R3197  27  [R0402]
R3198  27  [R0402]
R3199  27  [R0402]
R3200  27  [R0402]
R3201  27  [R0402]
R3202  27  [R0402]
R3203  27  [R0402]
R3204  27  [R0402]
R3205  27  [R0402]
R3206  27  [R0402]
R3207  27  [R0402]
R3208  27  [R0402]
R3209  27  [R0402]
R3210  27  [R0402]
R3577  0  [R0402]
R3578  0  [R0402]
R3579  0  [R0402]
R3580  0  [R0402]
R3581  0  [R0402]
R3582  0  [R0402]
R3583  0  [R0402]
R3584  0  [R0402]
R3585  0  [R0402]
R3586  0  [R0402]
R3587  0  [R0402]
R3588  0  [R0402]
R3589  0  [R0402]
R3590  0  [R0402]
R3591  0  [R0402]
R3592  0  [R0402]
R3593  0  [R0402]
R3594  0  [R0402]
R3595  0  [R0402]
R3596  0  [R0402]
R3597  0  [R0402]
R3598  0  [R0402]
R3599  0  [R0402]
R3600  0  [R0402]
sheet 027 LEVEL SHIFTER 1
C1111  1000PF  [C0402]
C1112  1000PF  [C0402]
C1113  1000PF  [C0402]
C1178  1000PF  [C0402]
C1179  1000PF  [C0402]
C1249  100PF  [C0201]
C1250  100PF  [C0201]
C1251  100PF  [C0201]
Q38  BSS138-7-F  [SOT23_GDSXC]
Q39  BSS138-7-F  [SOT23_GDSXC]
Q40  BSS138-7-F  [SOT23_GDSXC]
Q42  BSS138-7-F  [SOT23_GDSXC]
Q43  BSS138-7-F  [SOT23_GDSXC]
R3745  4.75K  [R0402]
R3746  10  [R0402]
R3747  4.75K  [R0402]
R3749  4.75K  [R0402]
R3750  10  [R0402]
R3751  4.75K  [R0402]
R3753  4.75K  [R0402]
R3754  10  [R0402]
R3755  4.75K  [R0402]
R3757  22  [R0402]
R3758  22  [R0402]
R3759  22  [R0402]
R4065  4.75K  [R0402]
R4066  10  [R0402]
R4067  4.75K  [R0402]
R4068  22  [R0402]
R4069  4.75K  [R0402]
R4070  10  [R0402]
R4071  4.75K  [R0402]
R4072  22  [R0402]
sheet 028 LEVEL SHIFTER 2
C1078  100NF  [C0402]
C1079  100NF  [C0402]
C1082  100NF  [C0402]
C1083  100NF  [C0402]
C1224  100NF  [C0402]
C1225  100NF  [C0402]
D4  PCA9517ADP  [TSSOP8_3]
Q50  DMG3415U-7  [SOT23_GDSXC]
Q51  DMN601WK-7  [SOT323_GDS_2-15X1-3]
R91  4.7K  [R0402]
R92  4.7K  [R0402]
R93  4.7K  [R0402]
R94  4.7K  [R0402]
R95  4.7K  [R0402]
R96  4.7K  [R0402]
R2833  4.7K  [R0402]
R2834  4.7K  [R0402]
R2835  4.7K  [R0402]
R2836  4.7K  [R0402]
R2837  4.7K  [R0402]
R2838  4.7K  [R0402]
R2918  4.7K  [R0402]
R2919  4.7K  [R0402]
R2920  4.7K  [R0402]
R2921  4.7K  [R0402]
R2922  4.7K  [R0402]
R2923  4.7K  [R0402]
R2924  4.7K  [R0402]
R2925  4.7K  [R0402]
R2926  4.7K  [R0402]
R2927  4.7K  [R0402]
R2928  4.7K  [R0402]
R2929  4.7K  [R0402]
R3332  33  [R0402]
R3333  33  [R0402]
R3334  33  [R0402]
R3335  33  [R0402]
R3511  22  [R0402]
R3512  22  [R0402]
R3513  22  [R0402]
R3514  22  [R0402]
R3515  22  [R0402]
R3516  22  [R0402]
R3517  22  [R0402]
R3518  22  [R0402]
R3519  22  [R0402]
R3520  22  [R0402]
R3521  22  [R0402]
R3522  22  [R0402]
R3523  22  [R0402]
R3524  22  [R0402]
R3525  22  [R0402]
R3526  22  [R0402]
R3527  22  [R0402]
R3528  22  [R0402]
R3529  22  [R0402]
R3530  22  [R0402]
R3531  22  [R0402]
R3532  22  [R0402]
R3533  22  [R0402]
R3534  22  [R0402]
R4290  10K  [R0402]
R4292  0  [R0402]
R4293  0  [R0603]
U71  74LVC07APW  [TSSOP14]  (sections A,B,C,D,E,F)
U72  74LVC07APW  [TSSOP14]  (sections A,B,C,D,E,F)
sheet 029 M.2_A
C12  100NF  [C0402]
C15  100NF  [C0402]
C89  100NF  [C0402]
C158  1UF  [C0402]
C159  10UF  [C0603]
C160  1UF  [C0402]
C161  10UF  [C0603]
C162  1UF  [C0402]
C163  10UF  [C0603]
C1085  100NF  [C0402]
C1086  100NF  [C0402]
R2777  4.7K  [R0402]
R2840  4.7K  [R0402]
R3619  4.7K  [R0402]
R3620  22  [R0402]
R3621  22  [R0402]
R3622  4.7K  [R0402]
R3623  0.005  [R1206XK]
R3625  10  [R0402]
R3626  10  [R0402]
R3899  4.7K  [R0402]
R4016  22  [R0402]
R4098  4.7K  [R0201]
R4099  4.7K  [R0201]
R4100  4.7K  [R0201]
R4101  4.7K  [R0201]
R4234  0  [R0402]
R4235  0  [R0402]
R4262  4.7K  [R0402]
R4294  0  [R0402]
TP3  TP  [TP26D10]
TP4  TP  [TP26D10]
TP25  TP  [TP26D10]
TP26  TP  [TP26D10]
TP49  TP  [TP26D10]
U73  INA231AIYFFR  [BGA12_0-4_1-388X1-6445]
sheet 030 M.2_B
J4  SCONN134_MDT670M01005  [CON_F134S2H4D4S_P0-5W7-55_LUVXA]  (sections A,B)

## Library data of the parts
C759 C761 C769 C771-C776 C1074 C1075 C1086 C1174 C1224 C1225 = CAP_NP: CAP CHIP 100NF 50V(+-10%,X7R,0402); CLASS: DISCRETE; MATERIAL: X7R; Manuf_PN: CC0402KRX7R9BB104; Manuf_name: YAGEO CORPORATION; Manuftr: YGO; Part_Type: *LF_C0402; TOLERANCE: 10%; VOLTAGE: 50V
C970 C971 C1175 = CAP_NP: CAP CHIP 0.01U 50V(+-10%,X7R,0402); CLASS: DISCRETE; MATERIAL: X7R; Manuf_PN: WBM155R71H103K; Manuf_name: MURATA ERIE N.A. INC TAIWAN BRANCH Okayama Murata Mfg.Co.,Ltd.; Manuftr: MUR; Part_Type: *LF_C0402; TOLERANCE: 10%; VOLTAGE: 50V
C969 C1114 C1172 C1173 C1176 = CAP_NP: CAP CHIP 22U 10V(+-20%,X6S,0805)MUR; CLASS: DISCRETE; MATERIAL: X6S; Manuf_PN: GRM21BC81A226M; Manuf_name: MURATA ERIE N.A. INC TAIWAN BRANCH Okayama Murata Mfg.Co.,Ltd.Wakura Murata Mfg.; Manuftr: MUR; Part_Type: *LF_C0805; TOLERANCE: 20%; VOLTAGE: 10V
C158 C160 C162 C760 C762 C959 C960 C964-C968 C972 C973 C1223 = CAP_NP: CAP CHIP 1UF 25V(+-10%,X6S,0402); CLASS: DISCRETE; MATERIAL: X6S; Manuf_PN: GRM155C81E105K; Manuf_name: MURATA ERIE N.A. INC TAIWAN BRANCH Okayama Murata Mfg.Co..Ltd.Wakura Murata Mfg.; Manuftr: MUR; Part_Type: *LF_C0402; TOLERANCE: 10%; VOLTAGE: 25V
J60 = SCONN5_1051330011: CONN SMD MICRO USB 5P 1R FS(P0.65,H6.7); CLASS: IO; ESD_CDM: NA; ESD_HBM: NA; ESD_MM: NA; MATERIAL: IO; MSD: NA; Manuf_PN: 105133-0011; Manuf_name: MOLEX TAIWAN LTD.DONGGUAN MOLEX INTERCONNECT CO., LTD; Manuftr: MLX; PIN_LENGTH_LONG_PIN: 91 MILS; PIN_LENGTH_SHORT_PIN: 91 MILS; Part_Type: *LF_Connector
R3274 R3280 R3332-R3335 R4324-R4327 = R: RES CHIP 33 1/16W +-5% (0402); CLASS: DISCRETE; MATERIAL: CHIP; Manuf_PN: RR0510S-330-JN; Manuf_name: CYNTEC CO.. LTD.; Manuftr: CYN; Part_Type: *LF_Resistor; TOLERANCE: 5%; WATTAGE: 1/16W
R2964 R2966 R3275 R3277 = R: RES CHIP 4.75K 1/16W +-1%(0402); CLASS: DISCRETE; MATERIAL: CHIP; Manuf_PN: RR0510S-4751-FN; Manuf_name: CYNTEC CO.. LTD.; Manuftr: CYN; Not_insert: NI; Part_Type: *LF_Resistor; TOLERANCE: 1%; WATTAGE: 1/16W
R2967 R2968 R3276 R3278 R3279 R3745 R3747 R3749 R3751 R3753 R3755 R4065 R4067 R4069 R4071 = R: RES CHIP 4.75K 1/16W +-1%(0402); CLASS: DISCRETE; MATERIAL: CHIP; Manuf_PN: RR0510S-4751-FN; Manuf_name: CYNTEC CO.. LTD.; Manuftr: CYN; Part_Type: *LF_Resistor; TOLERANCE: 1%; WATTAGE: 1/16W
R4383 R4384 = R: RES CHIP 0 1/16W +-5%(0402)EF; BOM: AST2300; CLASS: DISCRETE; FPLIST: R0402,R0402-0201; MATERIAL: CHIP; Manuf_PN: WR04X000PTR; Manuf_name: WALSIN TECHNOLOGY CORPORATION; Manufacturer: CYN; Manuftr: WTC; Part_Type: *LF_Resistor; TOLERANCE: 5%; WATTAGE: 1/16W
U66 = TXS0102DCUR: IC OTHER (8P) TXS0102DCUR(VSSOP); CLASS: IC; MATERIAL: IC; Manuf_name: TEXAS INSTRUMENTS SUPPLY CO.,; Manuftr: TIC; Part_Type: *LF_Chipset
C954 C955 = CAP_NP: CAP CHIP 12P 50V(+-5%.C0G.0402); CLASS: DISCRETE; FPLIST: C0402,C0402-0201; MATERIAL: C0G; Manuf_PN: CC0402N120J3SST-S; Manuf_name: RTECH TECHNOLOGY CO..LTD.(Compostar); Manuftr: RHT; Part_Type: *LF_C0402; TOLERANCE: 5%; VOLTAGE: 50V
C961 C974 = CAP_NP: CAP CHIP 1UF 25V(+-10%,X6S,0402); CLASS: DISCRETE; MATERIAL: X6S; Manuf_PN: GRM155C81E105K; Manuf_name: MURATA ERIE N.A. INC TAIWAN BRANCH Okayama Murata Mfg.Co..Ltd.Wakura Murata Mfg.; Manuftr: MUR; Not_insert: NI; Part_Type: *LF_C0402; TOLERANCE: 10%; VOLTAGE: 25V
C1078 C1079 C1085 C1226 C1227 = CAP_NP: CAP CHIP 100NF 50V(+-10%,X7R,0402); CLASS: DISCRETE; MATERIAL: X7R; Manuf_PN: CC0402KRX7R9BB104; Manuf_name: YAGEO CORPORATION; Manufacturer: AVX; Manuftr: YGO; Part_Type: *LF_C0402; TOLERANCE: 10%; VOLTAGE: 50V
L11 L13 = L: EMI FILTER BLM15PX471SN1D (470,1000MA); CLASS: DISCRETE; Current_Amp: 1000MA; ESD_CDM: N/A; ESD_HBM: N/A; ESD_MM: N/A; MATERIAL: IND; MSD: NA; Manuf_name: MURATA ERIE N.A. INC TAIWAN BRANCH Okayama Murata; Manuftr: MUR; PIN_LENGTH_LONG_PIN: 0 MILS; PIN_LENGTH_SHORT_PIN: 0 MILS; Part_Type: *LF_Inductor
R3227 = R: RES CHIP 1M 1/16W +-5% (0402); CLASS: DISCRETE; MATERIAL: CHIP; Manuf_PN: RR0510S-105-JN; Manuf_name: CYNTEC CO.. LTD.; Manuftr: CYN; Part_Type: *LF_Resistor; TOLERANCE: 5%; WATTAGE: 1/16W
R3228 = R: RES CHIP 1.69K 1/16W +-1%(0402); CLASS: DISCRETE; MATERIAL: CHIP; Manuf_PN: CR021K69F002S; Manuf_name: RTECH TECHNOLOGY CO..LTD.(Compostar); Manuftr: RHT; Part_Type: *LF_Resistor; TOLERANCE: 1%; WATTAGE: 1/16W
R3230 R3232 R3235 R3236 = R: RES CHIP 1K 1/16W +-1% (0402); CLASS: DISCRETE; MATERIAL: CHIP; Manuf_PN: RR0510S-102-FN; Manuf_name: CYNTEC CO.. LTD.; Manuftr: CYN; Not_insert: NI; Part_Type: *LF_Resistor; TOLERANCE: 1%; WATTAGE: 1/16W
R2969 R2971 R3231 R3233 R3234 R3237 R3240 = R: RES CHIP 1K 1/16W +-1% (0402); CLASS: DISCRETE; MATERIAL: CHIP; Manuf_PN: RR0510S-102-FN; Manuf_name: CYNTEC CO.. LTD.; Manuftr: CYN; Part_Type: *LF_Resistor; TOLERANCE: 1%; WATTAGE: 1/16W
R3238 R3239 = R: RES CHIP 2.2K 1/16W +-5%(0402)EF; CLASS: DISCRETE; FPLIST: R0402,R0402-0201; MATERIAL: CHIP; Manuf_PN: RC0402JR-072K2P; Manuf_name: YAGEO CORPORATION; Manuftr: YGO; Part_Type: *LF_Resistor; TOLERANCE: 5%; WATTAGE: 1/16W
R3241 = R: RES CHIP 100 1/16W +-5% (0402); CLASS: DISCRETE; MATERIAL: CHIP; Manuf_PN: RR0510S-101-JN; Manuf_name: CYNTEC CO.. LTD.; Manuftr: CYN; Part_Type: *LF_Resistor; TOLERANCE: 5%; WATTAGE: 1/16W
U61 = ZL30281LDF1: IC OTHER(32P)ZL30281LDF1(QFN); CLASS: IC; ESD_CDM: N/A; ESD_HBM: N/A; ESD_MM: N/A; MATERIAL: IC; MSD: NA; Manuf_name: Microsemi Corporation ( Microsemi Taiwan); Manuftr: MST; PIN_LENGTH_LONG_PIN: 0 MILS; PIN_LENGTH_SHORT_PIN: 0 MILS; Part_Type: *LF_Chipset
D4 U106 = PCA9517DP: IC OTHER (8P) PCA9517ADP(TSSOP8); CLASS: IC; MATERIAL: IC; Manuf_name: NXP semiconductors; Manuftr: NXP; Part_Type: *LF_Chipset
Y2 = X_4S_CX3225SB25000D0FPLCC: XTAL SMD 25MHZ(20PPM,10PF)7M25090007; CLASS: IO; ESD_CDM: N/A; ESD_HBM: N/A; ESD_MM: N/A; MATERIAL: MISC; MSD: Level-1; Manuf_PN: 7M25090007; Manuf_name: TAIWAN X'TAL CORPATION (TXC Corporation); Manuftr: TXC; PIN_LENGTH_LONG_PIN: 0 MILS; PIN_LENGTH_SHORT_PIN: 0 MILS; Part_Type: *LF_Misc
C770 = CAP_NP: CAP CHIP 10UF 6.3V(+-20%,X6S,0402); CLASS: DISCRETE; MATERIAL: X6S; Manuf_PN: GRM155C80J106M; Manuf_name: MURATA ERIE N.A. INC TAIWAN BRANCH Okayama Murata Mfg.Co.,; Manuftr: MUR; Part_Type: *LF_C0402; TOLERANCE: 20%; VOLTAGE: 6.3V
L6 = L: EMI FILTER GMLB-201209-0330P-N8(330,3A); CLASS: DISCRETE; Current_Amp: 3A; MATERIAL: IND; Manuf_PN: GMLB-201209-0330P-N8; Manuf_name: MAG. LAYERS; Manuftr: MAG; Part_Type: *LF_Inductor
R2916 R2917 = R: RES CHIP 2.2 1/10W +-1%(0603); CLASS: DISCRETE; MATERIAL: CHIP; Manuf_PN: WR06W2R20FTL; Manuf_name: WALSIN TECHNOLOGY CORPORATION; Manuftr: WTC; Part_Type: *LF_Resistor; TOLERANCE: 1%; WATTAGE: 1/10W
R2958 R2959 R3511-R3534 R3757-R3759 R4016 R4068 R4072 = R: RES CHIP 22 1/16W +-1%(0402); CLASS: DISCRETE; MATERIAL: CHIP; Manuf_PN: CR0222R0F002S; Manuf_name: RTECH TECHNOLOGY CO..LTD. (Compostar); Manuftr: RHT; Part_Type: *LF_Resistor; TOLERANCE: 1%; WATTAGE: 1/16W
R2960 = R: RES CHIP 100K 1/16W +-1% (0402); CLASS: DISCRETE; MATERIAL: CHIP; Manuf_PN: RR0510S-104-FN; Manuf_name: CYNTEC CO.. LTD.; Manuftr: CYN; Not_insert: NI; Part_Type: *LF_Resistor; TOLERANCE: 1%; WATTAGE: 1/16W
R2961 = R: RES CHIP 150 1/16W +-1%(0402); CLASS: DISCRETE; MATERIAL: CHIP; Manuf_PN: RR0510S-151-FN; Manuf_name: CYNTEC CO.. LTD.; Manuftr: CYN; Part_Type: *LF_Resistor; TOLERANCE: 1%; WATTAGE: 1/16W
R2963 R2970 = R: RES CHIP 1K 1/20W +-1%(0201); CLASS: DISCRETE; MATERIAL: CHIP; Manuf_PN: RC0201FR-071KL; Manuf_name: YAGEO CORPORATION; Manuftr: YGO; Not_insert: NI; Part_Type: *LF_Resistor; TOLERANCE: 1%; WATTAGE: 1/20W
U47 = 9ZXL1231EKILF1KW: IC OTHER(64P)9ZXL1231EKILF-1K/W(VFQFPN); CLASS: IC; ESD_CDM: no; ESD_HBM: no; ESD_MM: no; MATERIAL: IC; MSD: NA; Manuf_name: INTEGRATED DEVICE TECHNOLOGY,INC.; Manuftr: IDT; PIN_LENGTH_LONG_PIN: 0 MILS; PIN_LENGTH_SHORT_PIN: 0 MILS; Part_Type: *LF_Chipset
R3187-R3210 = R: RES CHIP 27 1/16W +-5%(0402); BOM: AST2300; CLASS: DISCRETE; MATERIAL: CHIP; Manuf_PN: RTT02270JTH; Manuf_name: RALEC ELECTRONIC CO.; Manufacturer: CYN; Manuftr: RLC; Part_Type: *LF_Resistor; TOLERANCE: 5%; WATTAGE: 1/16W
R3577-R3600 R4234 R4235 = R: RESISTOR CHIP 0 1/16W +-5%(0402); CLASS: DISCRETE; MATERIAL: CHIP; Manuf_PN: RR0510X-000-XN; Manuf_name: CYNTEC CO.. LTD.; Manuftr: CYN; Not_insert: NI; Part_Type: *LF_Resistor; TOLERANCE: 5%; WATTAGE: 1/16W
C1111-C1113 C1178 C1179 = CAP_NP: CAP CHIP 1000P 50V(+-5%.X7R.0402); CLASS: DISCRETE; MATERIAL: X7R; Manuf_PN: C1005X7R102JGT; Manuf_name: ACER PERIPHERALS INC.(Darfon Electronics Corp.); Manuftr: API; Part_Type: *LF_C0402; TOLERANCE: 5%; VOLTAGE: 50V
C1249-C1251 = CAP_NP: CAP CHIP 100PF 16V(+-10%,X7R,0201); CLASS: DISCRETE; MATERIAL: X7R; Manuf_PN: GRM033R71C101K; Manuf_name: MURATA ERIE N.A. INC TAIWAN BRANCH Okayama Murata Mfg.Co.,Ltd.Wakura Murata Mfg.; Manuftr: MUR; Part_Type: *LF_C0201; TOLERANCE: 10%; VOLTAGE: 16V
Q38-Q40 Q42 Q43 = MOSFET_N_0: TRANS MOSFET BSS138-7-F(50V,0.2A); CLASS: IC; MATERIAL: IC; Manuf_name: DIODES TAIWAN CO.,LTD.; Manuftr: DDS; Part_Type: *LF_Semiconductor
R3625 R3626 R3746 R3750 R3754 R4066 R4070 = R: RES CHIP 10 1/16W +-1%(0402); CLASS: DISCRETE; MATERIAL: CHIP; Manuf_PN: RM04FTN10R0; Manuf_name: TA-I TECHNOLOGY CO..LTD.; Manuftr: TAI; Part_Type: *LF_Resistor; TOLERANCE: 1%; WATTAGE: 1/16W
C12 C15 C89 C1082 C1083 = CAP_NP: CAP CHIP 100NF 50V(+-10%,X7R,0402); CLASS: DISCRETE; MATERIAL: X7R; Manuf_PN: CC0402KRX7R9BB104; Manuf_name: YAGEO CORPORATION; Manufacturer: MUR; Manuftr: YGO; Part_Type: *LF_C0402; TOLERANCE: 10%; VOLTAGE: 50V
Q50 = MOSFET_PCH_GDS: TRANS MOS DMG3415U-7(-20V,-4A,0.9W)SOT23; CLASS: IC; MATERIAL: IC; Manuf_name: DIODES TAIWAN CO.,LTD.(Kai Hong Shanghai); Manuftr: DDS; Part_Type: *LF_Semiconductor
Q51 = MOSFET_NCH_GATE_PRO_DIODE_GDS: TRANS MOSFET DMN601WK-7(60V,300MA)SOT323; CLASS: IC; MATERIAL: IC; Manuf_name: DIODES TAIWAN CO.,LTD.(Kai Hong Shanghai); Manuftr: DDS; Part_Type: *LF_Semiconductor
R91-R96 R2918-R2922 R2924 = R: RES CHIP 4.7K 1/16W +-1%(0402); CLASS: DISCRETE; MATERIAL: CHIP; Manuf_PN: RTT024701FTH; Manuf_name: RALEC ELECTRONIC CO.; Manufacturer: CYN; Manuftr: RLC; Not_insert: NI; Part_Type: *LF_Resistor; TOLERANCE: 1%; WATTAGE: 1/16W
R2833-R2838 R2923 R2925-R2929 = R: RES CHIP 4.7K 1/16W +-1%(0402); CLASS: DISCRETE; MATERIAL: CHIP; Manuf_PN: RTT024701FTH; Manuf_name: RALEC ELECTRONIC CO.; Manufacturer: CYN; Manuftr: RLC; Part_Type: *LF_Resistor; TOLERANCE: 1%; WATTAGE: 1/16W
R4290 = R: RES CHIP 10K 1/16W 5%(0402); CLASS: DISCRETE; MATERIAL: CHIP; Manuf_PN: RR0510S-103-JN; Manuf_name: CYNTEC CO.. LTD.; Manuftr: CYN; Part_Type: *LF_Resistor; TOLERANCE: 5%; WATTAGE: 1/16W
R4292 R4294 = R: RESISTOR CHIP 0 1/16W +-5%(0402); CLASS: DISCRETE; MATERIAL: CHIP; Manuf_PN: RR0510X-000-XN; Manuf_name: CYNTEC CO.. LTD.; Manuftr: CYN; Part_Type: *LF_Resistor; TOLERANCE: 5%; WATTAGE: 1/16W
R4293 = R: RESISTOR CHIP 0 1/10W+-5%(0603); CLASS: DISCRETE; MATERIAL: CHIP; Manuf_PN: CRCW06030000Z0EA; Manuf_name: DALE ELECTRONICS.INC.; Manuftr: DAL; Not_insert: NI; Part_Type: *LF_Resistor; TOLERANCE: 5%; WATTAGE: 1/10W
U71 U72 = 74LVC07: IC(14P) 74LVC07APW(TSSOP); CLASS: IC; MATERIAL: IC; Manuf_name: PHILIPS TAIWAN LTD..; Manuftr: PHI; Part_Type: *LF_Chipset
C159 C161 C163 = CAP_NP: CAP CHIP 10U 16V(+-20%,X6S,0603); CLASS: DISCRETE; MATERIAL: X6S; Manuf_PN: GRM188C81C106M; Manuf_name: MURATA ERIE N.A. INC TAIWAN BRANCH Okayama Murata Mfg.Co..Ltd. Wakura Murata Mfg; Manuftr: MUR; Part_Type: *LF_C0603; TOLERANCE: 20%; VOLTAGE: 16V
R2777 R2840 = R: RES CHIP 4.7K 1/16W +-5% (0402); CLASS: DISCRETE; MATERIAL: CHIP; Manuf_PN: RR0510S-472-JN; Manuf_name: CYNTEC CO.. LTD.; Manufacturer: CYN; Manuftr: CYN; Part_Type: *LF_Resistor; TOLERANCE: 5%; WATTAGE: 1/16W
R3619 R3622 R3899 = R: RES CHIP 4.7K 1/16W +-5% (0402); CLASS: DISCRETE; MATERIAL: CHIP; Manuf_PN: RR0510S-472-JN; Manuf_name: CYNTEC CO.. LTD.; Manuftr: CYN; Part_Type: *LF_Resistor; TOLERANCE: 5%; WATTAGE: 1/16W
R3620 R3621 = R: RES CHIP 22 1/16W +-1%(0402); BOM: AST2300; CLASS: DISCRETE; MATERIAL: CHIP; Manuf_PN: CR0222R0F002S; Manuf_name: RTECH TECHNOLOGY CO..LTD. (Compostar); Manufacturer: CYN; Manuftr: RHT; Part_Type: *LF_Resistor; TOLERANCE: 1%; WATTAGE: 1/16W
R3623 = R: RES CHIP  0.005  1W +-1%(1206); CLASS: DISCRETE; ESD_CDM: NA; ESD_HBM: NA; ESD_MM: NA; MATERIAL: CHIP; MSD: NA; Manuf_PN: RLM12FTCMR005; Manuf_name: TA-I TECHNOLOGY CO.,LTD.; Manuftr: TAI; PIN_LENGTH_LONG_PIN: 0 MILS; PIN_LENGTH_SHORT_PIN: 0 MILS; Part_Type: *LF_Resistor; TOLERANCE: 1%; WATTAGE: 1W
R4098 R4099 R4101 = R: RES CHIP 4.7K(1/20W,+-5%,0201); CLASS: DISCRETE; MATERIAL: CHIP; Manuf_PN: RR0306S-472-JN; Manuf_name: CYNTEC CO., LTD.; Manuftr: CYN; Not_insert: NI; Part_Type: *LF_Resistor; TOLERANCE: 5%; WATTAGE: 1/20W
R4100 = R: RES CHIP 4.7K(1/20W,+-5%,0201); CLASS: DISCRETE; MATERIAL: CHIP; Manuf_PN: RR0306S-472-JN; Manuf_name: CYNTEC CO., LTD.; Manuftr: CYN; Part_Type: *LF_Resistor; TOLERANCE: 5%; WATTAGE: 1/20W
R4262 = R: RES CHIP 4.7K 1/16W +-5% (0402); CLASS: DISCRETE; MATERIAL: CHIP; Manuf_PN: RR0510S-472-JN; Manuf_name: CYNTEC CO.. LTD.; Manufacturer: CYN; Manuftr: CYN; Not_insert: NI; Part_Type: *LF_Resistor; TOLERANCE: 5%; WATTAGE: 1/16W
TP3 TP4 TP25 TP26 TP49 = TP: TEST POINT (TP26D10) DIP(DRILL10MILS); ALT_SYMBOLS: TOP:TP26D10;BOTTOM:TP30D10; CLASS: IO; Cost: CPU; DIP_SMD: DIP; MATERIAL: MISC; Not_insert: NI; Part_Type: Misc; SUBSYS: CPU_CONN
U73 = INA231AIYFFR: IC OTHER (12P) INA231AIYFFR (DSBGA); CLASS: IC; ESD_CDM: 1000; ESD_HBM: 2500; ESD_MM: 150; MATERIAL: IC; MSD: Level-1; Manuf_name: TEXAS INSTRUMENTS SUPPLY CO.,; Manuftr: TIC; PIN_LENGTH_LONG_PIN: 0 MILS; PIN_LENGTH_SHORT_PIN: 0 MILS; Part_Type: *LF_Chipset
J4 = SCONN134_MDT670M01005: CONN SMD HOUSING 150P 2R FR(P0.5,H6.7); CLASS: IO; ESD_CDM: N/A; ESD_HBM: N/A; ESD_MM: N/A; MATERIAL: IO; MSD: NA; Manuf_PN: MDT670M01005; Manuf_name: AMPHENOL EAST ASIA LIMITED (Amphenol-TCS) (Shangh; Manuftr: APL; PIN_LENGTH_LONG_PIN: 20MILS; PIN_LENGTH_SHORT_PIN: 20MILS; Part_Type: *LF_Connector

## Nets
GND: C12.2 C15.2 C89.2 C158.2 C159.2 C160.2 C161.2 C162.2 C163.2 C759.2 C760.2 C761.2 C762.2 C769.2 C770.2 C771.2 C772.2 C773.2 C774.2 C775.2 C776.2 C954.2 C955.2 C959.2 C960.2 C961.2 C964.2 C965.2 C966.2 C967.2 C968.2 C969.2 C972.2 C973.2 C974.2 C1074.1 C1075.1 C1078.2 C1079.2 C1082.2 C1083.2 C1085.2 C1111.2 C1112.2 C1113.2 C1114.2 C1172.2 C1173.2 C1174.2 C1175.2 C1176.2 C1178.2 C1179.2 C1223.2 C1224.1 C1225.2 C1226.2 C1227.2 C1249.2 C1250.2 C1251.2 D4.4(GND) J4.B1(GND18) J4.B3(GND19) J4.B9(GND20) J4.B15(GND21) J4.B21(GND22) J4.B27(GND23) J4.B32(NC10) J4.B33(GND24) J4.B38(NC13) J4.B39(GND25) J4.B45(GND26) J4.B51(GND27) J4.B57(GND28) J4.B71(GND29) J4.B75(GND31) J4.G3 J4.G4 J60.5(GND) J60.G1 J60.G2 J60.G3 Q51.S R91.2 R92.2 R93.2 R94.2 R95.2 R96.2 R2918.2 R2919.2 R2920.2 R2921.2 R2922.2 R2924.2 R2960.1 R2964.2 R2966.2 R2969.2 R2971.2 R3231.2 R3233.2 R3235.2 R3237.2 R3240.2 R3577.2 R3578.2 R3579.2 R3580.2 R3581.2 R3582.2 R3583.2 R3584.2 R3585.2 R3586.2 R3587.2 R3588.2 R3589.2 R3590.2 R3591.2 R3592.2 R3593.2 R3594.2 R3595.2 R3596.2 R3597.2 R3598.2 R3599.2 R3600.2 R4100.2 R4101.2 R4235.1 U47.2(GNDA) U47.7(GND0) U47.23(GND1) U47.33(GND2) U47.41(GND3) U47.48(GND4) U47.58(GND5) U47.65(EPAD) U61.TH(GND) U66.2(GND) U71.7(GND) U72.7(GND) U73.C1(GND) U106.4(GND) Y2.2(G1) Y2.4(G2) ; also on sheet 12 13 17 25 26 27 28 29 30 31 32 33 34 35 36 37 38 39 40 41 42 43 44 45 46 47 48 49 50 52 53 54 55 56 57 58 61 62 63 64 65 66 67
P1V8: C959.1 C960.1 C961.1 C1074.2 C1079.1 C1082.1 C1083.1 D4.1(VCCA) L13.1 R3277.1 R3278.1 R3279.1 R3745.1 R3746.2 R3749.1 R3750.2 R3753.1 R3754.2 R4065.1 R4066.2 R4069.1 R4070.2 R4234.1 U61.18(AVDD18) U61.29(DVDD18) U66.3(VCCA) U71.14(VCC) U72.14(VCC) ; also on sheet 17 25 26 27 28 29 30 31 32 33 34 35 36 37 44 49 50 53 58 62 65 67
P3V3: C1225.1 Q50.D R2833.1 R2834.1 R2835.1 R2836.1 R2837.1 R2838.1 R2923.1 R2925.1 R2926.1 R2927.1 R2928.1 R2929.1 R4293.2 ; also on sheet 44
P3V3_DB1200: C769.1 C770.1 C771.1 C772.1 C773.1 C774.1 C775.1 C776.1 L6.2 R2916.1 R2917.1 R2963.1 R2967.1 R2968.1 R2970.1 U47.24(VDD0) U47.25(VDDIO1) U47.32(VDDIO2) U47.40(VDD1) U47.49(VDDIO3) U47.56(VDDIO4) U47.57(VDD2)
P3V3_DB1200_VDDA: C759.1 C760.1 R2916.2 U47.1(VDDA)
P3V3_DB1200_VDDR: C761.1 C762.1 R2917.2 U47.8(VDDR)
P3V3_M2A: R3623.2 R3625.1 U73.D1(BUS) ; also on sheet 39
P3V3_M2A_L: C12.1 C15.1 C89.1 C158.1 C159.1 C160.1 C161.1 C162.1 C163.1 J4.B2(3.3V_10) J4.B4(3.3V_11) J4.B12(3.3V_12) J4.B14(3.3V_13) J4.B16(3.3V_14) J4.B18(3.3V_15) J4.B70(3.3V_16) J4.B72(3.3V_17) J4.B74(3.3V_18) R2777.2 R2840.1 R3623.1 R3626.1 R4098.1 R4099.1 R4262.2
P3V3_STBY: C968.1 C1075.2 C1078.1 C1085.1 C1174.1 C1175.1 C1176.1 C1223.1 C1224.2 C1226.1 C1227.1 D4.8(VCCB) J60.1(VBUS) L6.1 L11.1 Q50.S R3230.1 R3232.1 R3234.1 R3236.1 R3238.1 R3239.1 R3275.1 R3276.1 R3619.1 R3622.1 R3747.1 R3751.1 R3755.1 R3899.2 R4067.1 R4071.1 R4290.1 R4293.1 U61.3(DVDD33) U66.7(VCCB) U73.B1(VS) U106.1(VCCA) U106.8(VCCB) ; also on sheet 12 17 25 26 27 28 29 30 31 32 33 34 35 36 37 38 39 40 41 42 43 44 45 46 47 48 49 50 52 53 54 55 56 57 58 61 67
VDD_P1V8_ZL30281: C972.1 C973.1 C974.1 L13.2 U61.12(AVDD18) U61.13(AVDD18) U61.17(AVDD18)
VDD_P3V3_ZL30281: C964.1 C965.1 C966.1 C967.1 C969.1 C1114.1 C1172.1 C1173.1 L11.2 U61.9(VDDXO33) U61.16(VDDO3) U61.19(VDDO2) U61.22(AVDD33) U61.25(VDDO1)
CLK_100M_DB1200_M2A_DN: R3188.1 U47.18(DIF0#)
CLK_100M_DB1200_M2A_DP: R3187.1 U47.17(DIF0)
CLK_100M_DB1200_M2A_R_DN: J4.B53(NC25) R3188.2 R3578.1
CLK_100M_DB1200_M2A_R_DP: J4.B55(NC26) R3187.2 R3577.1
CLK_100M_DB1200_M2B_DN: R3190.1 U47.22(DIF1#)
CLK_100M_DB1200_M2B_DP: R3189.1 U47.21(DIF1)
CLK_100M_DB1200_M2B_R_DN: R3190.2 R3580.1 ; also on sheet 25
CLK_100M_DB1200_M2B_R_DP: R3189.2 R3579.1 ; also on sheet 25
CLK_100M_DB1200_M2C_DN: R3192.1 U47.27(DIF2#)
CLK_100M_DB1200_M2C_DP: R3191.1 U47.26(DIF2)
CLK_100M_DB1200_M2C_R_DN: R3192.2 R3582.1 ; also on sheet 26
CLK_100M_DB1200_M2C_R_DP: R3191.2 R3581.1 ; also on sheet 26
CLK_100M_DB1200_M2D_DN: R3194.1 U47.31(DIF3#)
CLK_100M_DB1200_M2D_DP: R3193.1 U47.30(DIF3)
CLK_100M_DB1200_M2D_R_DN: R3194.2 R3584.1 ; also on sheet 27
CLK_100M_DB1200_M2D_R_DP: R3193.2 R3583.1 ; also on sheet 27
CLK_100M_DB1200_M2E_DN: R3196.1 U47.35(DIF4#)
CLK_100M_DB1200_M2E_DP: R3195.1 U47.34(DIF4)
CLK_100M_DB1200_M2E_R_DN: R3196.2 R3586.1 ; also on sheet 28
CLK_100M_DB1200_M2E_R_DP: R3195.2 R3585.1 ; also on sheet 28
CLK_100M_DB1200_M2F_DN: R3198.1 U47.39(DIF5#)
CLK_100M_DB1200_M2F_DP: R3197.1 U47.38(DIF5)
CLK_100M_DB1200_M2F_R_DN: R3198.2 R3588.1 ; also on sheet 29
CLK_100M_DB1200_M2F_R_DP: R3197.2 R3587.1 ; also on sheet 29
CLK_100M_DB1200_M2G_DN: R3200.1 U47.43(DIF6#)
CLK_100M_DB1200_M2G_DP: R3199.1 U47.42(DIF6)
CLK_100M_DB1200_M2G_R_DN: R3200.2 R3590.1 ; also on sheet 30
CLK_100M_DB1200_M2G_R_DP: R3199.2 R3589.1 ; also on sheet 30
CLK_100M_DB1200_M2H_DN: R3202.1 U47.47(DIF7#)
CLK_100M_DB1200_M2H_DP: R3201.1 U47.46(DIF7)
CLK_100M_DB1200_M2H_R_DN: R3202.2 R3592.1 ; also on sheet 31
CLK_100M_DB1200_M2H_R_DP: R3201.2 R3591.1 ; also on sheet 31
CLK_100M_DB1200_M2I_DN: R3204.1 U47.51(DIF8#)
CLK_100M_DB1200_M2I_DP: R3203.1 U47.50(DIF8)
CLK_100M_DB1200_M2I_R_DN: R3204.2 R3594.1 ; also on sheet 32
CLK_100M_DB1200_M2I_R_DP: R3203.2 R3593.1 ; also on sheet 32
CLK_100M_DB1200_M2J_DN: R3206.1 U47.55(DIF9#)
CLK_100M_DB1200_M2J_DP: R3205.1 U47.54(DIF9)
CLK_100M_DB1200_M2J_R_DN: R3206.2 R3596.1 ; also on sheet 33
CLK_100M_DB1200_M2J_R_DP: R3205.2 R3595.1 ; also on sheet 33
CLK_100M_DB1200_M2K_DN: R3208.1 U47.60(DIF10#)
CLK_100M_DB1200_M2K_DP: R3207.1 U47.59(DIF10)
CLK_100M_DB1200_M2K_R_DN: R3208.2 R3598.1 ; also on sheet 34
CLK_100M_DB1200_M2K_R_DP: R3207.2 R3597.1 ; also on sheet 34
CLK_100M_DB1200_M2L_DN: R3210.1 U47.64(DIF11#)
CLK_100M_DB1200_M2L_DP: R3209.1 U47.63(DIF11)
CLK_100M_DB1200_M2L_R_DN: R3210.2 R3600.1 ; also on sheet 35
CLK_100M_DB1200_M2L_R_DP: R3209.2 R3599.1 ; also on sheet 35
CLK_100M_PESW_D_C_DN: C971.2 R3241.2 ; also on sheet 67
CLK_100M_PESW_D_C_DP: C970.2 R3241.1 ; also on sheet 67
CLK_100M_PESW_D_DN: C971.1 U61.23(OC1N)
CLK_100M_PESW_D_DP: C970.1 U61.24(OC1P)
CLK_100M_PESW_S3_DB1200_C_DN: U47.10(DIF_IN#) ; also on sheet 67
CLK_100M_PESW_S3_DB1200_C_DP: U47.9(DIF_IN) ; also on sheet 67
CLKBUF_M2A_OE_N: U47.19(vOE0#) ; also on sheet 43
CLKBUF_M2B_OE_N: U47.20(vOE1#) ; also on sheet 43
CLKBUF_M2C_OE_N: U47.28(vOE2#) ; also on sheet 43
CLKBUF_M2D_OE_N: U47.29(vOE3#) ; also on sheet 43
CLKBUF_M2E_OE_N: U47.36(vOE4#) ; also on sheet 43
CLKBUF_M2F_OE_N: U47.37(vOE5#) ; also on sheet 43
CLKBUF_M2G_OE_N: U47.44(vOE6#) ; also on sheet 43
CLKBUF_M2H_OE_N: U47.45(vOE7#) ; also on sheet 43
CLKBUF_M2I_OE_N: U47.52(vOE8#) ; also on sheet 43
CLKBUF_M2J_OE_N: U47.53(vOE9#) ; also on sheet 43
CLKBUF_M2K_OE_N: U47.61(vOE10#) ; also on sheet 43
CLKBUF_M2L_OE_N: U47.62(vOE11#) ; also on sheet 43
COM_CPLD_M2A_RX: J4.B46(NC17) ; also on sheet 52
COM_CPLD_M2A_TX: R4294.1 ; also on sheet 52
COM_CPLD_M2A_TX_R: J4.B48(NC18) R4294.2
FM_CLKBUF_DB1200_EN: R2960.2 R2961.2 ; also on sheet 67
FM_CLKBUF_DB1200_EN_R: R2961.1 U47.6(^CKPWRGD_PD#)
I2C_PESW_M2A_EN: R3529.1 ; also on sheet 17
I2C_PESW_M2A_EN_LVC: R3511.2 ; also on sheet 38
I2C_PESW_M2A_EN_LVC_R: R91.1 R2833.2 R3511.1 U72.2(OUT)
I2C_PESW_M2A_EN_R: R3529.2 U72.1(IN)
I2C_PESW_M2B_EN: R3530.1 ; also on sheet 17
I2C_PESW_M2B_EN_LVC: R3512.2 ; also on sheet 38
I2C_PESW_M2B_EN_LVC_R: R92.1 R2834.2 R3512.1 U72.4(OUT)
I2C_PESW_M2B_EN_R: R3530.2 U72.3(IN)
I2C_PESW_M2C_EN: R3531.1 ; also on sheet 17
I2C_PESW_M2C_EN_LVC: R3513.2 ; also on sheet 38
I2C_PESW_M2C_EN_LVC_R: R93.1 R2835.2 R3513.1 U72.6(OUT)
I2C_PESW_M2C_EN_R: R3531.2 U72.5(IN)
I2C_PESW_M2D_EN: R3532.1 ; also on sheet 17
I2C_PESW_M2D_EN_LVC: R3514.2 ; also on sheet 38
I2C_PESW_M2D_EN_LVC_R: R94.1 R2836.2 R3514.1 U72.8(OUT)
I2C_PESW_M2D_EN_R: R3532.2 U72.9(IN)
I2C_PESW_M2E_EN: R3533.1 ; also on sheet 17
I2C_PESW_M2E_EN_LVC: R3516.2 ; also on sheet 38
I2C_PESW_M2E_EN_LVC_R: R95.1 R2837.2 R3516.1 U72.10(OUT)
I2C_PESW_M2E_EN_R: R3533.2 U72.11(IN)
I2C_PESW_M2F_EN: R3534.1 ; also on sheet 17
I2C_PESW_M2F_EN_LVC: R3520.2 ; also on sheet 38
I2C_PESW_M2F_EN_LVC_R: R96.1 R2838.2 R3520.1 U72.12(OUT)
I2C_PESW_M2F_EN_R: R3534.2 U72.13(IN)
I2C_PESW_M2G_EN: R3523.1 ; also on sheet 17
I2C_PESW_M2G_EN_LVC: R3515.2 ; also on sheet 38
I2C_PESW_M2G_EN_LVC_R: R2918.1 R2923.2 R3515.1 U71.2(OUT)
I2C_PESW_M2G_EN_R: R3523.2 U71.1(IN)
I2C_PESW_M2H_EN: R3524.1 ; also on sheet 17
I2C_PESW_M2H_EN_LVC: R3517.2 ; also on sheet 38
I2C_PESW_M2H_EN_LVC_R: R2919.1 R2925.2 R3517.1 U71.4(OUT)
I2C_PESW_M2H_EN_R: R3524.2 U71.3(IN)
I2C_PESW_M2I_EN: R3525.1 ; also on sheet 17
I2C_PESW_M2I_EN_LVC: R3518.2 ; also on sheet 38
I2C_PESW_M2I_EN_LVC_R: R2920.1 R2926.2 R3518.1 U71.6(OUT)
I2C_PESW_M2I_EN_R: R3525.2 U71.5(IN)
I2C_PESW_M2J_EN: R3526.1 ; also on sheet 17
I2C_PESW_M2J_EN_LVC: R3519.2 ; also on sheet 38
I2C_PESW_M2J_EN_LVC_R: R2921.1 R2927.2 R3519.1 U71.8(OUT)
I2C_PESW_M2J_EN_R: R3526.2 U71.9(IN)
I2C_PESW_M2K_EN: R3527.1 ; also on sheet 17
I2C_PESW_M2K_EN_LVC: R3521.2 ; also on sheet 38
I2C_PESW_M2K_EN_LVC_R: R2922.1 R2928.2 R3521.1 U71.10(OUT)
I2C_PESW_M2K_EN_R: R3527.2 U71.11(IN)
I2C_PESW_M2L_EN: R3528.1 ; also on sheet 17
I2C_PESW_M2L_EN_LVC: R3522.2 ; also on sheet 38
I2C_PESW_M2L_EN_LVC_R: R2924.1 R2929.2 R3522.1 U71.12(OUT)
I2C_PESW_M2L_EN_R: R3528.2 U71.13(IN)
I2C_PESW_MULTI_CONFIG_ADD0: Q38.D(DRAIN) R3747.2 ; also on sheet 46
I2C_PESW_MULTI_CONFIG_ADD0_L: C1249.1 R3757.1 ; also on sheet 17
I2C_PESW_MULTI_CONFIG_ADD0_L_R: Q38.S(SOURCE) R3745.2 R3757.2
I2C_PESW_MULTI_CONFIG_ADD1: Q39.D(DRAIN) R3751.2 ; also on sheet 46
I2C_PESW_MULTI_CONFIG_ADD1_L: C1250.1 R3758.1 ; also on sheet 17
I2C_PESW_MULTI_CONFIG_ADD1_L_R: Q39.S(SOURCE) R3749.2 R3758.2
I2C_PESW_MULTI_CONFIG_ADD2: Q40.D(DRAIN) R3755.2 ; also on sheet 46
I2C_PESW_MULTI_CONFIG_ADD2_L: C1251.1 R3759.1 ; also on sheet 17
I2C_PESW_MULTI_CONFIG_ADD2_L_R: Q40.S(SOURCE) R3753.2 R3759.2
I2C_PESW_MULTI_CONFIG_ADD3: Q42.D(DRAIN) R4067.2 ; also on sheet 46
I2C_PESW_MULTI_CONFIG_ADD3_L: R4068.1 ; also on sheet 17
I2C_PESW_MULTI_CONFIG_ADD3_L_R: Q42.S(SOURCE) R4065.2 R4068.2
I2C_PESW_MULTI_CONFIG_ADD4: Q43.D(DRAIN) R4071.2 ; also on sheet 46
I2C_PESW_MULTI_CONFIG_ADD4_L: R4072.1 ; also on sheet 17
I2C_PESW_MULTI_CONFIG_ADD4_L_R: Q43.S(SOURCE) R4069.2 R4072.2
JTAG_CPLD_M2A_TCK: J4.B28(GND17) ; also on sheet 51
JTAG_CPLD_M2A_TDI: J4.B24(NC7) ; also on sheet 51
JTAG_CPLD_M2A_TDO: J4.B26(NC8) ; also on sheet 51
JTAG_CPLD_M2A_TMS: J4.B67(NC27) ; also on sheet 51
JTAG_CPLD_M2A_TRST: J4.B20(NC6) ; also on sheet 51
M2A_LED: J4.B10(NC5) R2840.2
M2A_VIO_CFG: J4.B73(GND30) R4235.2
P3E_PESW_M2A_RX0_DN: J4.B41(PERN4) ; also on sheet 15
P3E_PESW_M2A_RX0_DP: J4.B43(PERP4) ; also on sheet 15
P3E_PESW_M2A_RX1_DN: J4.B29(PERN5) ; also on sheet 15
P3E_PESW_M2A_RX1_DP: J4.B31(PERP5) ; also on sheet 15
P3E_PESW_M2A_RX2_DN: J4.B17(PERN6) ; also on sheet 15
P3E_PESW_M2A_RX2_DP: J4.B19(PERP6) ; also on sheet 15
P3E_PESW_M2A_RX3_DN: J4.B5(PERN7) ; also on sheet 15
P3E_PESW_M2A_RX3_DP: J4.B7(PERP7) ; also on sheet 15
P3E_PESW_M2A_TX0_C_DN: J4.B47(PETN4) ; also on sheet 15
P3E_PESW_M2A_TX0_C_DP: J4.B49(PETP4) ; also on sheet 15
P3E_PESW_M2A_TX1_C_DN: J4.B35(PETN5) ; also on sheet 15
P3E_PESW_M2A_TX1_C_DP: J4.B37(PETP5) ; also on sheet 15
P3E_PESW_M2A_TX2_C_DN: J4.B23(PETN6) ; also on sheet 15
P3E_PESW_M2A_TX2_C_DP: J4.B25(PETP6) ; also on sheet 15
P3E_PESW_M2A_TX3_C_DN: J4.B11(PETN7) ; also on sheet 15
P3E_PESW_M2A_TX3_C_DP: J4.B13(PETP7) ; also on sheet 15
PD_DB1200_SMB_SA0: R2963.2 R2969.1 U47.11(vSADR0_tri)
PD_DB1200_SMB_SA1: R2970.2 R2971.1 U47.14(vSADR1_tri)
PD_M2A_PWRDIS: J4.B6(NC3) R4099.2 R4100.1
PD_ZL30281_AC0: R3230.2 R3231.1 U61.28(AC0)
PD_ZL30281_AC1: R3232.2 R3233.1 U61.27(AC1)
PD_ZL30281_IF1: R3236.2 R3237.1 U61.1(IF1||MISO)
PD_ZL30281_TEST: R3240.1 U61.26(TEST)
PU_DB1200_100M: R2964.1 R2967.2 U47.4(^100M_133M#)
PU_DB1200_HI_BW: R2966.1 R2968.2 U47.5(^HIBW_BYPM_LOBW#)
PU_INA231_M2A_A0: R3619.2 U73.B3(A0)
PU_INA231_M2A_A1: R3622.2 U73.C3(A1)
PU_M2A_CLKREQ_N: J4.B52(NC20) R2777.1
PU_M2A_PLA_S3_N: J4.B30(NC9) R4262.1
PU_M2A_VIO_1V8: J4.B22(GND16) R4234.2
PU_P3V3_STBY_Q50_G: Q50.G Q51.D R4290.2
PU_PESW_MULTI_CONFIG_ADD0: C1111.1 Q38.G(GATE) R3746.1
PU_PESW_MULTI_CONFIG_ADD1: C1112.1 Q39.G(GATE) R3750.1
PU_PESW_MULTI_CONFIG_ADD2: C1113.1 Q40.G(GATE) R3754.1
PU_PESW_MULTI_CONFIG_ADD3: C1178.1 Q42.G(GATE) R4066.1
PU_PESW_MULTI_CONFIG_ADD4: C1179.1 Q43.G(GATE) R4070.1
PU_TXS_OE: R3278.2 U66.6(OE)
PU_ZL30281_IF0: R3234.2 R3235.1 U61.32(IF0||CSN)
PWRGD_CLK_ZL30281: U61.4(READY) ; also on sheet 67
PWRGD_P1V8: D4.5(ENABLE) R4292.2 U61.30(RSTN) U106.5(ENABLE) ; also on sheet 38 58
PWRGD_P1V8_R: Q51.G R4292.1
RESERVED_M2A_PLN_N: J4.B8(NC4) R4098.2 R4101.1
RST_PESW_M2A_LVC_N: J4.B50(NC19) ; also on sheet 44
SMB_M2A_ALERT_N: J4.B44(NC16) ; also on sheet 49
SMB_M2A_INA231_ALRT_N: R4016.2 ; also on sheet 46
SMB_M2A_INA231_ALRT_N_R: R3899.1 R4016.1 U73.A3(ALERT)
SMB_M2A_INA231_CLK_R1: R3620.1 U73.A1(SCL)
SMB_M2A_INA231_DAT_R1: R3621.1 U73.A2(SDA)
SMB_M2A_P1V8_CLK: J4.B40(NC14) R3620.2 ; also on sheet 36
SMB_M2A_P1V8_DAT: J4.B42(NC15) R3621.2 ; also on sheet 36
SMB_PESW_3V3SB_CLK: R3334.2 ; also on sheet 46
SMB_PESW_3V3SB_CLK_R1: D4.7(SCLB) R3334.1
SMB_PESW_3V3SB_DAT: R3335.2 ; also on sheet 46
SMB_PESW_3V3SB_DAT_R1: D4.6(SDAB) R3335.1
SMB_PESW_P1V8_CLK: R3332.1 ; also on sheet 17
SMB_PESW_P1V8_CLK_R1: D4.2(SCLA) R3332.2
SMB_PESW_P1V8_DAT: R3333.1 ; also on sheet 17
SMB_PESW_P1V8_DAT_R1: D4.3(SDAA) R3333.2
SMB_SENSOR_3V3SB_CLK: R2959.1 ; also on sheet 45 46
SMB_SENSOR_3V3SB_CLK_R1: R4326.2 ; also on sheet 43 45 46 61
SMB_SENSOR_3V3SB_CLK_R3: R4326.1 U106.7(SCLB)
SMB_SENSOR_3V3SB_DAT: R2958.1 ; also on sheet 45 46
SMB_SENSOR_3V3SB_DAT_R1: R4327.2 ; also on sheet 43 45 46 61
SMB_SENSOR_3V3SB_DAT_R3: R4327.1 U106.6(SDAB)
SMB_SENSOR_DB1200_CLK_R1: R2959.2 U47.13(SMBCLK)
SMB_SENSOR_DB1200_DAT_R1: R2958.2 U47.12(SMBDAT)
SMB_SENSOR_ZL30281_CLK: R4324.1 U61.31(SCL||SCLK)
SMB_SENSOR_ZL30281_CLK_R1: R3239.2 R4324.2 U106.2(SCLA)
SMB_SENSOR_ZL30281_DAT: R4325.1 U61.2(SDA||MOSI)
SMB_SENSOR_ZL30281_DAT_R1: R3238.2 R4325.2 U106.3(SDAA)
TP_M2A_MFG_CLK: J4.B58(NC23) TP4.1
TP_M2A_MFG_DAT: J4.B56(NC22) TP3.1
TP_PEWAKE_M2A: J4.B54(NC21) TP49.1
TP_USB2_M2A_DN: J4.B36(NC12) TP26.1
TP_USB2_M2A_DP: J4.B34(NC11) TP25.1
UART_PESW_CPLD_USIN: R4384.2 ; also on sheet 52
UART_PESW_CPLD_USOUT: R4383.2 ; also on sheet 52
UART_PESW_USIN: R3279.2 U66.5(A1) ; also on sheet 17
UART_PESW_USIN_3V3SB: R3274.1 U66.8(B1)
UART_PESW_USIN_3V3SB_R: J60.3(D+) R3274.2 R3276.2 R4384.1
UART_PESW_USOUT: R3277.2 U66.4(A2) ; also on sheet 17
UART_PESW_USOUT_3V3SB: R3280.1 U66.1(B2)
UART_PESW_USOUT_3V3SB_R: J60.2(D-) R3275.2 R3280.2 R4383.1
VSENSE_P3V3_M2A_INA231_INN: C1086.2 R3626.2 U73.D2(IN-)
VSENSE_P3V3_M2A_INA231_INP: C1086.1 R3625.2 U73.D3(IN+)
XTAL_25M_ZL30281_XA: C954.1 R3227.1 U61.10(XA) Y2.1(X1)
XTAL_25M_ZL30281_XB: C955.1 R3228.1 Y2.3(X2)
XTAL_25M_ZL30281_XB_R: R3227.2 R3228.2 U61.11(XB)

Not connected (* = marked no-connect by the designer): J4 B68(NC24) B69(NC28); J60 4(ID); U47 3(NC1)* 15(FBOUT_NC#)* 16(FBOUT_NC)*; U61 5(DNC)* 6(DNC)* 7(DNC)* 8(DNC)* 14(DNC)* 15(OC3)* 20(OC2P)* 21(OC2N)*; U73 B2(NC)* C2(NC)*

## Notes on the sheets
sheet 18
- UART 3-PIN HEADER
- Note:
  Change 3 pin header to micro USB
  to connect to debug board
- CAD Note:
  R4383,R4384 place at near j60
- LEVEL SHIFTER (1.8V TO 3.3V STBY)
- PCIE SWITCH UART
sheet 19
- SMBus (8-Bit) Address:0xDA
- 25MHz Crystal
- Termination (CML to LVDS)
- Note: R3241 plase close to the input pins of PM8545
- I2C ISOLATION (BIC TO CLOCK GEN)
- 100MHz CLOCK GEN
sheet 20
- PCIE CLOCK BUFFER
- Default
  1:HBW  Mode
  0:LBW  Mode
- SMBus (8-Bit) Address:0xD8
- CLOCK BUFFER 1
sheet 21
- CLOCK BUFFER 2
sheet 22
- CAD Note:
  C1249~C1251 place near R3433~R3435
  and share GND via with them.
- LEVEL SHIFTER 1
sheet 23
- I2C ISOLATION (BIC TO PM8545)
- Level Shifter (PM8545 to Power Switch)
- Note: Using P3V3 normal power to avoid unexpected
  output when VCC is 0V.
- LEVEL SHIFTER 2
sheet 24
- CAD Note:
  J4 is dual M.2 connector.
- SMBus (8-Bit) Address:0x8A
- M.2_A
